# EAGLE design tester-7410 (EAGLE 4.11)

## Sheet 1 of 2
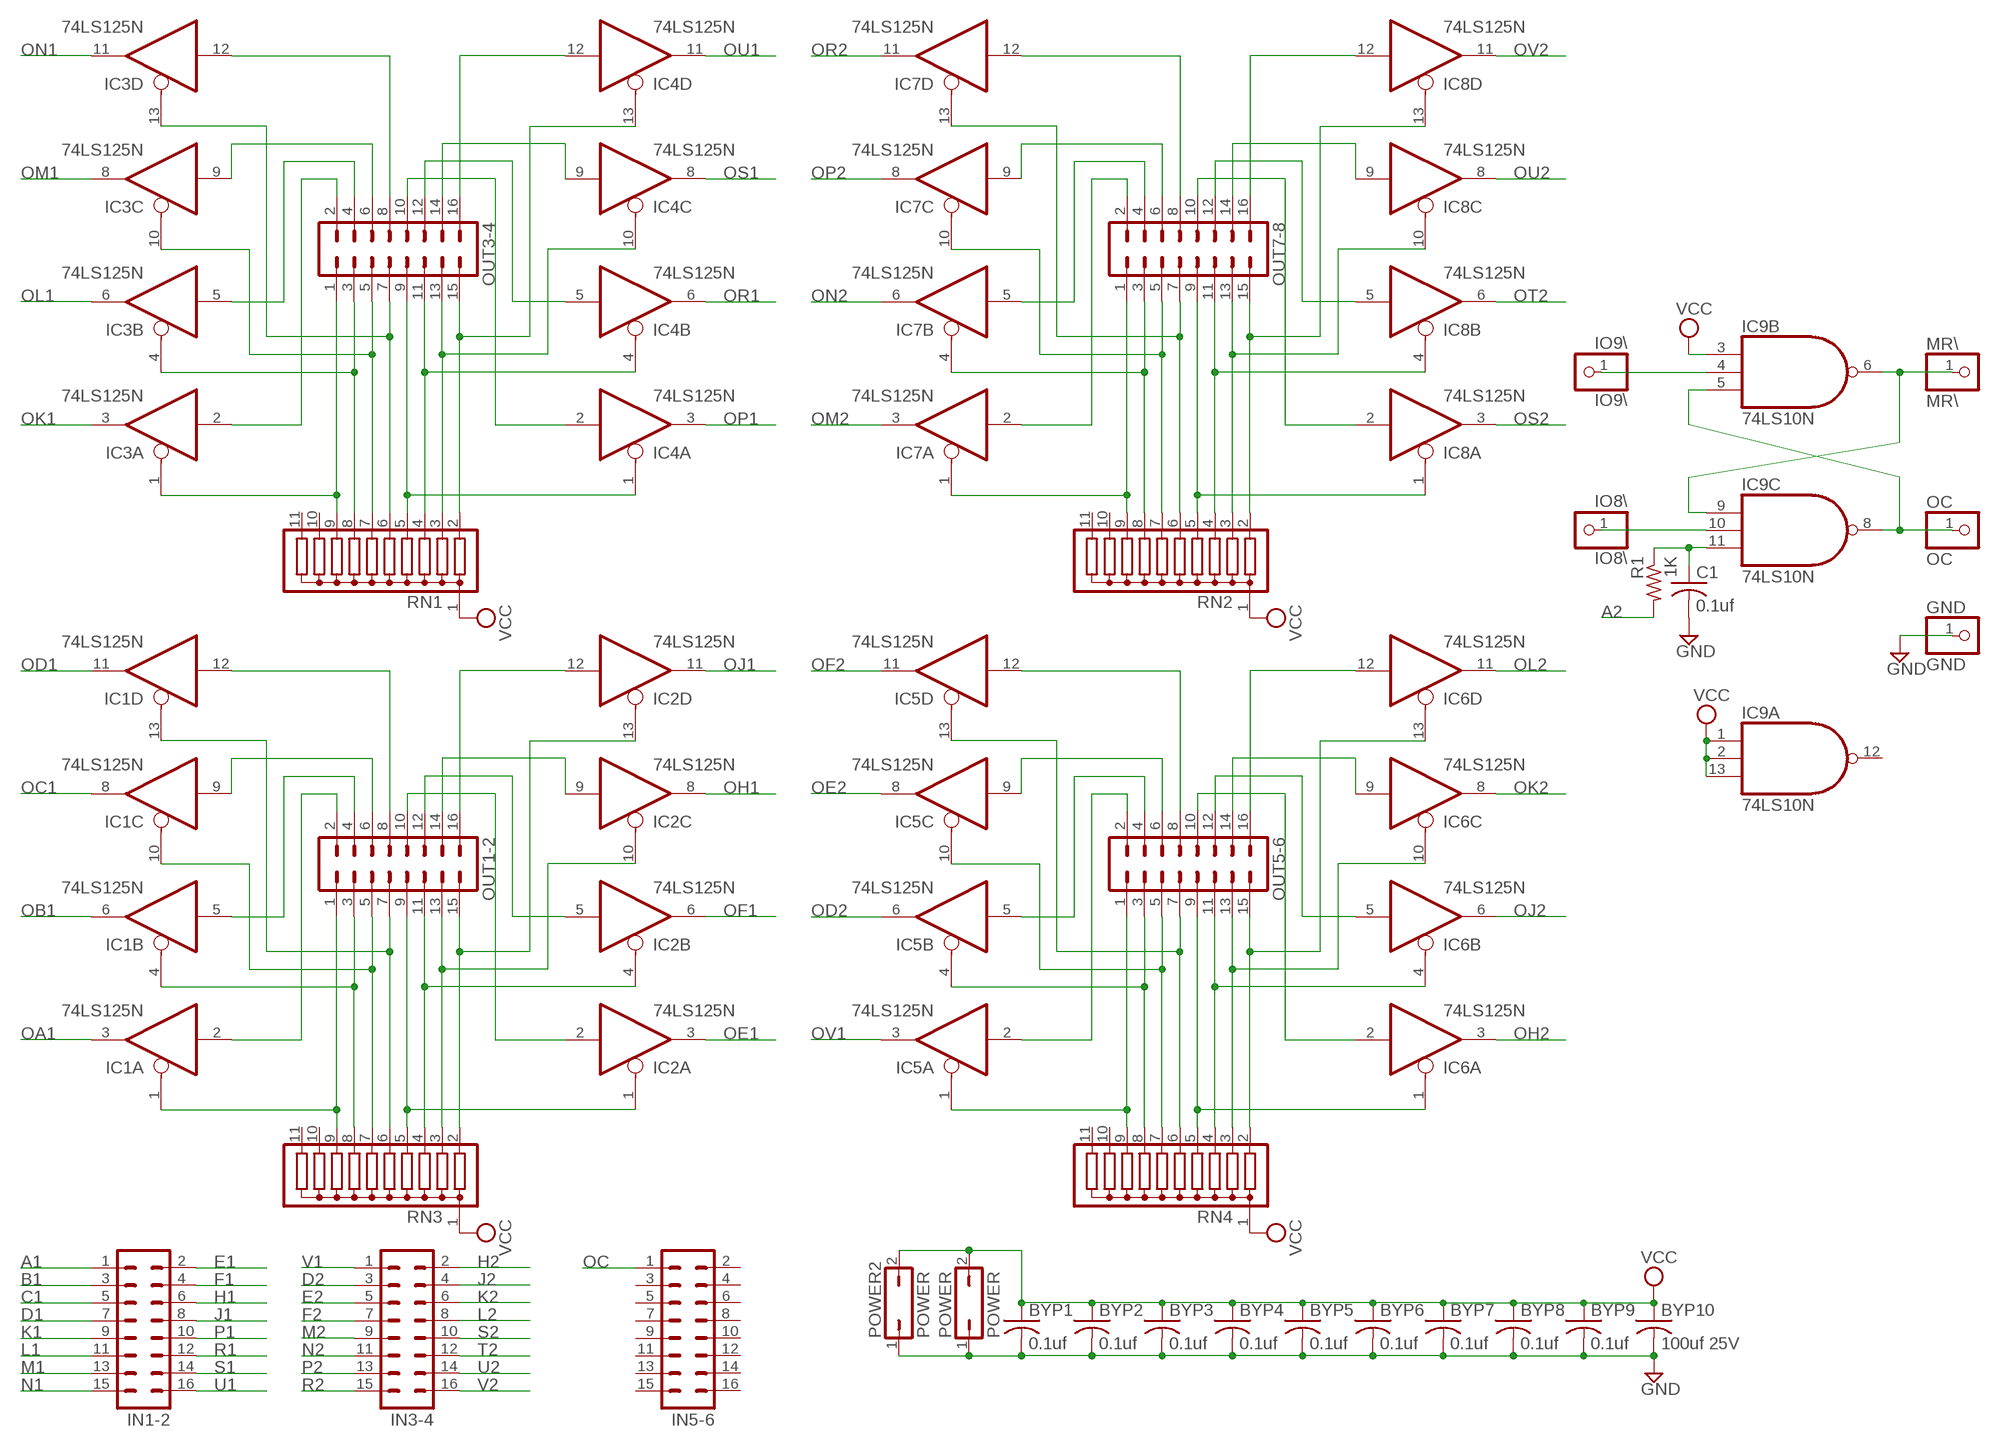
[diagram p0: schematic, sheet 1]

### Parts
BYP1  0.1uf  C-US050-025X075  [C050-025X075]
BYP2  0.1uf  C-US050-025X075  [C050-025X075]
BYP3  0.1uf  C-US050-025X075  [C050-025X075]
BYP4  0.1uf  C-US050-025X075  [C050-025X075]
BYP5  0.1uf  C-US050-025X075  [C050-025X075]
BYP6  0.1uf  C-US050-025X075  [C050-025X075]
BYP7  0.1uf  C-US050-025X075  [C050-025X075]
BYP8  0.1uf  C-US050-025X075  [C050-025X075]
BYP9  0.1uf  C-US050-025X075  [C050-025X075]
BYP10  100uf 25V  C-US150-064X183  [C150-064X183]
C1  0.1uf  C-US050-025X075  [C050-025X075]
GND  GND  PINHD-1X1  [1X01]
IC1  74LS125N  [DIL14]
IC2  74LS125N  [DIL14]
IC3  74LS125N  [DIL14]
IC4  74LS125N  [DIL14]
IC5  74LS125N  [DIL14]
IC6  74LS125N  [DIL14]
IC7  74LS125N  [DIL14]
IC8  74LS125N  [DIL14]
IC9  74LS10N  [DIL14]
IN1-2  MA08-2  [MA08-2]
IN3-4  MA08-2  [MA08-2]
IN5-6  MA08-2  [MA08-2]
IO8\  IO8\  PINHD-1X1  [1X01]
IO9\  IO9\  PINHD-1X1  [1X01]
MR\  MR\  PINHD-1X1  [1X01]
OC  OC  PINHD-1X1  [1X01]
OUT1-2  MA08-2  [MA08-2]
OUT3-4  MA08-2  [MA08-2]
OUT5-6  MA08-2  [MA08-2]
OUT7-8  MA08-2  [MA08-2]
POWER  POWER  JP1Q  [JP1]
POWER2  POWER  JP1Q  [JP1]
R1  1K  R-US_0207/10  [0207/10]
RN1  G10R  [SIL11]
RN2  G10R  [SIL11]
RN3  G10R  [SIL11]
RN4  G10R  [SIL11]

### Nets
A1: IN1-2.1 ; also sheet 2
A2: R1.2 ; also sheet 2
B1: IN1-2.3 ; also sheet 2
C1: IN1-2.5 ; also sheet 2
D1: IN1-2.7 ; also sheet 2
D2: IN3-4.3 ; also sheet 2
E1: IN1-2.2 ; also sheet 2
E2: IN3-4.5 ; also sheet 2
F1: IN1-2.4 ; also sheet 2
F2: IN3-4.7 ; also sheet 2
GND [Power]: BYP1.2 BYP2.2 BYP3.2 BYP4.2 BYP5.2 BYP6.2 BYP7.2 BYP8.2 BYP9.2 BYP10.2 C1.2 GND.1 POWER2.1 POWER.1 ; also sheet 2
H1: IN1-2.6 ; also sheet 2
H2: IN3-4.2 ; also sheet 2
IO8\: IC9.10(C:I1) IO8\.1
IO9\: IC9.4(B:I1) IO9\.1
J1: IN1-2.8 ; also sheet 2
J2: IN3-4.4 ; also sheet 2
K1: IN1-2.9 ; also sheet 2
K2: IN3-4.6 ; also sheet 2
L1: IN1-2.11 ; also sheet 2
L2: IN3-4.8 ; also sheet 2
M1: IN1-2.13 ; also sheet 2
M2: IN3-4.9 ; also sheet 2
MR\: IC9.6(B:O) IC9.9(C:I0) MR\.1
N1: IN1-2.15 ; also sheet 2
N2: IN3-4.11 ; also sheet 2
N$5: C1.1 IC9.11(C:I2) R1.1
N$53: IC1.1(A:OE) OUT1-2.1 RN3.9
N$54: IC1.4(B:OE) OUT1-2.3 RN3.8
N$55: IC1.10(C:OE) OUT1-2.5 RN3.7
N$56: IC1.13(D:OE) OUT1-2.7 RN3.6
N$57: IC1.2(A:I) OUT1-2.2
N$58: IC1.5(B:I) OUT1-2.4
N$59: IC1.9(C:I) OUT1-2.6
N$60: IC1.12(D:I) OUT1-2.8
N$61: IC5.4(B:OE) OUT5-6.3 RN4.8
N$62: IC2.10(C:OE) OUT1-2.13 RN3.3
N$63: IC2.4(B:OE) OUT1-2.11 RN3.4
N$64: IC2.1(A:OE) OUT1-2.9 RN3.5
N$65: IC2.2(A:I) OUT1-2.10
N$66: IC2.5(B:I) OUT1-2.12
N$67: IC2.9(C:I) OUT1-2.14
N$68: IC2.12(D:I) OUT1-2.16
N$138: IC5.13(D:OE) OUT5-6.7 RN4.6
N$139: IC2.13(D:OE) OUT1-2.15 RN3.2
N$140: IC5.2(A:I) OUT5-6.2
N$141: IC5.5(B:I) OUT5-6.4
N$142: IC5.9(C:I) OUT5-6.6
N$143: IC5.12(D:I) OUT5-6.8
N$144: IC6.10(C:OE) OUT5-6.13 RN4.3
N$145: IC6.4(B:OE) OUT5-6.11 RN4.4
N$146: IC6.1(A:OE) OUT5-6.9 RN4.5
N$147: IC6.2(A:I) OUT5-6.10
N$148: IC6.9(C:I) OUT5-6.14
N$149: IC6.12(D:I) OUT5-6.16
N$150: IC5.1(A:OE) OUT5-6.1 RN4.9
N$151: IC5.10(C:OE) OUT5-6.5 RN4.7
N$152: IC6.5(B:I) OUT5-6.12
N$153: IC6.13(D:OE) OUT5-6.15 RN4.2
N$154: IC3.4(B:OE) OUT3-4.3 RN1.8
N$155: IC3.13(D:OE) OUT3-4.7 RN1.6
N$156: IC3.2(A:I) OUT3-4.2
N$157: IC3.5(B:I) OUT3-4.4
N$158: IC3.9(C:I) OUT3-4.6
N$159: IC3.12(D:I) OUT3-4.8
N$160: IC4.10(C:OE) OUT3-4.13 RN1.3
N$161: IC4.4(B:OE) OUT3-4.11 RN1.4
N$162: IC4.1(A:OE) OUT3-4.9 RN1.5
N$163: IC4.2(A:I) OUT3-4.10
N$164: IC4.9(C:I) OUT3-4.14
N$165: IC4.12(D:I) OUT3-4.16
N$166: IC3.1(A:OE) OUT3-4.1 RN1.9
N$167: IC3.10(C:OE) OUT3-4.5 RN1.7
N$168: IC4.5(B:I) OUT3-4.12
N$169: IC4.13(D:OE) OUT3-4.15 RN1.2
N$170: IC7.4(B:OE) OUT7-8.3 RN2.8
N$171: IC7.13(D:OE) OUT7-8.7 RN2.6
N$172: IC7.2(A:I) OUT7-8.2
N$173: IC7.5(B:I) OUT7-8.4
N$174: IC7.9(C:I) OUT7-8.6
N$175: IC7.12(D:I) OUT7-8.8
N$176: IC8.10(C:OE) OUT7-8.13 RN2.3
N$177: IC8.4(B:OE) OUT7-8.11 RN2.4
N$178: IC8.1(A:OE) OUT7-8.9 RN2.5
N$179: IC8.2(A:I) OUT7-8.10
N$180: IC8.9(C:I) OUT7-8.14
N$181: IC8.12(D:I) OUT7-8.16
N$182: IC7.1(A:OE) OUT7-8.1 RN2.9
N$183: IC7.10(C:OE) OUT7-8.5 RN2.7
N$184: IC8.5(B:I) OUT7-8.12
N$185: IC8.13(D:OE) OUT7-8.15 RN2.2
OA1: IC1.3(A:O) ; also sheet 2
OB1: IC1.6(B:O) ; also sheet 2
OC: IC9.5(B:I2) IC9.8(C:O) IN5-6.1 OC.1
OC1: IC1.8(C:O) ; also sheet 2
OD1: IC1.11(D:O) ; also sheet 2
OD2: IC5.6(B:O) ; also sheet 2
OE1: IC2.3(A:O) ; also sheet 2
OE2: IC5.8(C:O) ; also sheet 2
OF1: IC2.6(B:O) ; also sheet 2
OF2: IC5.11(D:O) ; also sheet 2
OH1: IC2.8(C:O) ; also sheet 2
OH2: IC6.3(A:O) ; also sheet 2
OJ1: IC2.11(D:O) ; also sheet 2
OJ2: IC6.6(B:O) ; also sheet 2
OK1: IC3.3(A:O) ; also sheet 2
OK2: IC6.8(C:O) ; also sheet 2
OL1: IC3.6(B:O) ; also sheet 2
OL2: IC6.11(D:O) ; also sheet 2
OM1: IC3.8(C:O) ; also sheet 2
OM2: IC7.3(A:O) ; also sheet 2
ON1: IC3.11(D:O) ; also sheet 2
ON2: IC7.6(B:O) ; also sheet 2
OP1: IC4.3(A:O) ; also sheet 2
OP2: IC7.8(C:O) ; also sheet 2
OR1: IC4.6(B:O) ; also sheet 2
OR2: IC7.11(D:O) ; also sheet 2
OS1: IC4.8(C:O) ; also sheet 2
OS2: IC8.3(A:O) ; also sheet 2
OT2: IC8.6(B:O) ; also sheet 2
OU1: IC4.11(D:O) ; also sheet 2
OU2: IC8.8(C:O) ; also sheet 2
OV1: IC5.3(A:O) ; also sheet 2
OV2: IC8.11(D:O) ; also sheet 2
P1: IN1-2.10 ; also sheet 2
P2: IN3-4.13 ; also sheet 2
R1: IN1-2.12 ; also sheet 2
R2: IN3-4.15 ; also sheet 2
S1: IN1-2.14 ; also sheet 2
S2: IN3-4.10 ; also sheet 2
T2: IN3-4.12 ; also sheet 2
U1: IN1-2.16 ; also sheet 2
U2: IN3-4.14 ; also sheet 2
V1: IN3-4.1 ; also sheet 2
V2: IN3-4.16 ; also sheet 2
VCC [Power]: BYP1.1 BYP2.1 BYP3.1 BYP4.1 BYP5.1 BYP6.1 BYP7.1 BYP8.1 BYP9.1 BYP10.1 IC9.1(A:I0) IC9.2(A:I1) IC9.3(B:I0) IC9.13(A:I2) POWER2.2 POWER.2 RN1.1 RN2.1 RN3.1 RN4.1 ; also sheet 2
Unconnected: IC9.12(A:O) IN5-6.2 IN5-6.3 IN5-6.4 IN5-6.5 IN5-6.6 IN5-6.7 IN5-6.8 IN5-6.9 IN5-6.10 IN5-6.11 IN5-6.12 IN5-6.13 IN5-6.14 IN5-6.15 IN5-6.16 RN1.10 RN1.11 RN2.10 RN2.11 RN3.10 RN3.11 RN4.10 RN4.11

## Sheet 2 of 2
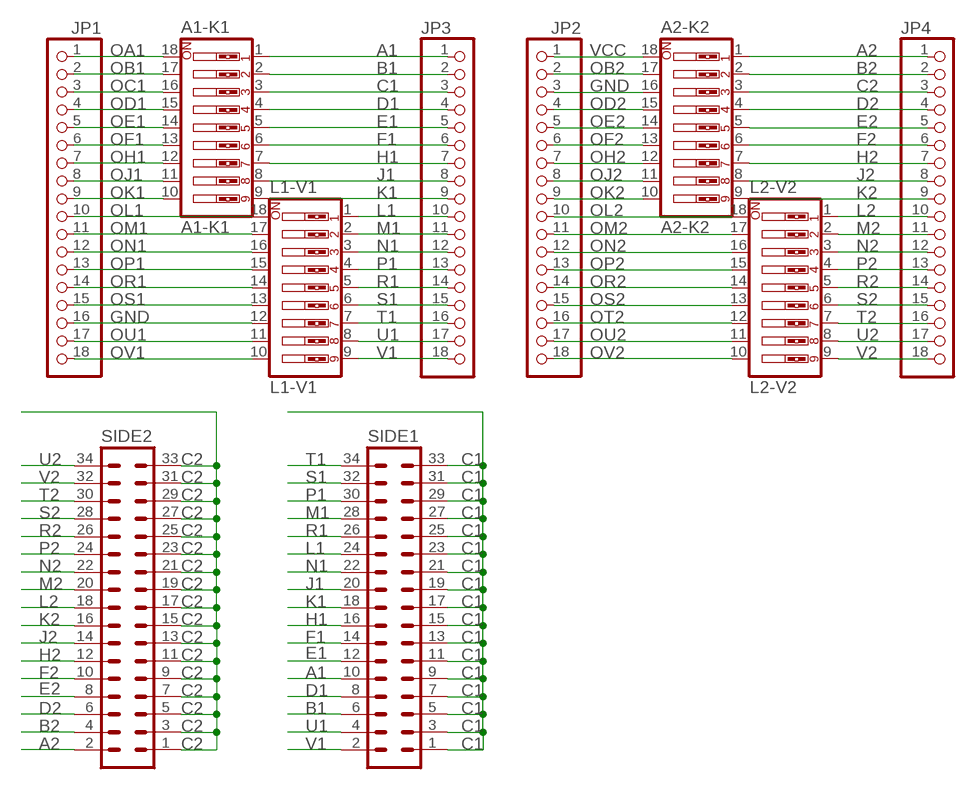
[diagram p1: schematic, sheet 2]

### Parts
A1-K1  A1-K1  SW_DIP-9  [EDG-09]
A2-K2  A2-K2  SW_DIP-9  [EDG-09]
JP1  PINHD-1X18  [1X18]
JP2  PINHD-1X18  [1X18]
JP3  PINHD-1X18  [1X18]
JP4  PINHD-1X18  [1X18]
L1-V1  L1-V1  SW_DIP-9  [EDG-09]
L2-V2  L2-V2  SW_DIP-9  [EDG-09]
SIDE1  MA17-2  [MA17-2]
SIDE2  MA17-2  [MA17-2]

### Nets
A1: A1-K1.1 JP3.1 SIDE1.10 ; also sheet 1
A2: A2-K2.1 JP4.1 SIDE2.2 ; also sheet 1
B1: A1-K1.2 JP3.2 SIDE1.6 ; also sheet 1
B2: A2-K2.2 JP4.2 SIDE2.4
C1: A1-K1.3 JP3.3 SIDE1.1 SIDE1.3 SIDE1.5 SIDE1.7 SIDE1.9 SIDE1.11 SIDE1.13 SIDE1.15 SIDE1.17 SIDE1.19 SIDE1.21 SIDE1.23 SIDE1.25 SIDE1.27 SIDE1.29 SIDE1.31 SIDE1.33 ; also sheet 1
C2: A2-K2.3 JP4.3 SIDE2.1 SIDE2.3 SIDE2.5 SIDE2.7 SIDE2.9 SIDE2.11 SIDE2.13 SIDE2.15 SIDE2.17 SIDE2.19 SIDE2.21 SIDE2.23 SIDE2.25 SIDE2.27 SIDE2.29 SIDE2.31 SIDE2.33
D1: A1-K1.4 JP3.4 SIDE1.8 ; also sheet 1
D2: A2-K2.4 JP4.4 SIDE2.6 ; also sheet 1
E1: A1-K1.5 JP3.5 SIDE1.12 ; also sheet 1
E2: A2-K2.5 JP4.5 SIDE2.8 ; also sheet 1
F1: A1-K1.6 JP3.6 SIDE1.14 ; also sheet 1
F2: A2-K2.6 JP4.6 SIDE2.10 ; also sheet 1
GND [Power]: A2-K2.16 JP1.16 JP2.3 L1-V1.12 ; also sheet 1
H1: A1-K1.7 JP3.7 SIDE1.16 ; also sheet 1
H2: A2-K2.7 JP4.7 SIDE2.12 ; also sheet 1
J1: A1-K1.8 JP3.8 SIDE1.20 ; also sheet 1
J2: A2-K2.8 JP4.8 SIDE2.14 ; also sheet 1
K1: A1-K1.9 JP3.9 SIDE1.18 ; also sheet 1
K2: A2-K2.9 JP4.9 SIDE2.16 ; also sheet 1
L1: JP3.10 L1-V1.1 SIDE1.24 ; also sheet 1
L2: JP4.10 L2-V2.1 SIDE2.18 ; also sheet 1
M1: JP3.11 L1-V1.2 SIDE1.28 ; also sheet 1
M2: JP4.11 L2-V2.2 SIDE2.20 ; also sheet 1
N1: JP3.12 L1-V1.3 SIDE1.22 ; also sheet 1
N2: JP4.12 L2-V2.3 SIDE2.22 ; also sheet 1
OA1: A1-K1.18 JP1.1 ; also sheet 1
OB1: A1-K1.17 JP1.2 ; also sheet 1
OB2: A2-K2.17 JP2.2
OC1: A1-K1.16 JP1.3 ; also sheet 1
OD1: A1-K1.15 JP1.4 ; also sheet 1
OD2: A2-K2.15 JP2.4 ; also sheet 1
OE1: A1-K1.14 JP1.5 ; also sheet 1
OE2: A2-K2.14 JP2.5 ; also sheet 1
OF1: A1-K1.13 JP1.6 ; also sheet 1
OF2: A2-K2.13 JP2.6 ; also sheet 1
OH1: A1-K1.12 JP1.7 ; also sheet 1
OH2: A2-K2.12 JP2.7 ; also sheet 1
OJ1: A1-K1.11 JP1.8 ; also sheet 1
OJ2: A2-K2.11 JP2.8 ; also sheet 1
OK1: A1-K1.10 JP1.9 ; also sheet 1
OK2: A2-K2.10 JP2.9 ; also sheet 1
OL1: JP1.10 L1-V1.18 ; also sheet 1
OL2: JP2.10 L2-V2.18 ; also sheet 1
OM1: JP1.11 L1-V1.17 ; also sheet 1
OM2: JP2.11 L2-V2.17 ; also sheet 1
ON1: JP1.12 L1-V1.16 ; also sheet 1
ON2: JP2.12 L2-V2.16 ; also sheet 1
OP1: JP1.13 L1-V1.15 ; also sheet 1
OP2: JP2.13 L2-V2.15 ; also sheet 1
OR1: JP1.14 L1-V1.14 ; also sheet 1
OR2: JP2.14 L2-V2.14 ; also sheet 1
OS1: JP1.15 L1-V1.13 ; also sheet 1
OS2: JP2.15 L2-V2.13 ; also sheet 1
OT2: JP2.16 L2-V2.12 ; also sheet 1
OU1: JP1.17 L1-V1.11 ; also sheet 1
OU2: JP2.17 L2-V2.11 ; also sheet 1
OV1: JP1.18 L1-V1.10 ; also sheet 1
OV2: JP2.18 L2-V2.10 ; also sheet 1
P1: JP3.13 L1-V1.4 SIDE1.30 ; also sheet 1
P2: JP4.13 L2-V2.4 SIDE2.24 ; also sheet 1
R1: JP3.14 L1-V1.5 SIDE1.26 ; also sheet 1
R2: JP4.14 L2-V2.5 SIDE2.26 ; also sheet 1
S1: JP3.15 L1-V1.6 SIDE1.32 ; also sheet 1
S2: JP4.15 L2-V2.6 SIDE2.28 ; also sheet 1
T1: JP3.16 L1-V1.7 SIDE1.34
T2: JP4.16 L2-V2.7 SIDE2.30 ; also sheet 1
U1: JP3.17 L1-V1.8 SIDE1.4 ; also sheet 1
U2: JP4.17 L2-V2.8 SIDE2.34 ; also sheet 1
V1: JP3.18 L1-V1.9 SIDE1.2 ; also sheet 1
V2: JP4.18 L2-V2.9 SIDE2.32 ; also sheet 1
VCC [Power]: A2-K2.18 JP2.1 ; also sheet 1

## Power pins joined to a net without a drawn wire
GND: IC1.7(P:GND) IC2.7(P:GND) IC3.7(P:GND) IC4.7(P:GND) IC5.7(P:GND) IC6.7(P:GND) IC7.7(P:GND) IC8.7(P:GND) IC9.7(P:GND)
VCC: IC1.14(P:VCC) IC2.14(P:VCC) IC3.14(P:VCC) IC4.14(P:VCC) IC5.14(P:VCC) IC6.14(P:VCC) IC7.14(P:VCC) IC8.14(P:VCC) IC9.14(P:VCC)

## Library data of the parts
A1-K1 A2-K2 L1-V1 L2-V2 = special:SW_DIP-9: DIP SWITCH
BYP1-BYP10 C1 = rcl:C-US: CAPACITOR, American symbol
GND IO8\ IO9\ MR\ OC = pinhead:PINHD-1X1: PIN HEADER
IC1-IC8 = 74xx-jameco:74*125: Quad bus BUFFER, 3-state
IC9 = 74xx-jameco:74*10: Triple 3-input NAND gate
IN1-2 IN3-4 IN5-6 OUT1-2 OUT3-4 OUT5-6 OUT7-8 = con-lstb:MA08-2: PIN HEADER
JP1-JP4 = pinhead:PINHD-1X18: PIN HEADER
POWER POWER2 = jumper:JP1Q: JUMPER
R1 = rcl:R-US_: RESISTOR, American symbol
RN1-RN4 = resistor-sil:G10R: SIL RESISTOR
SIDE1 SIDE2 = con-lstb:MA17-2: PIN HEADER

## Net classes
1 Power: width 0.305 mm, drill 0.305 mm

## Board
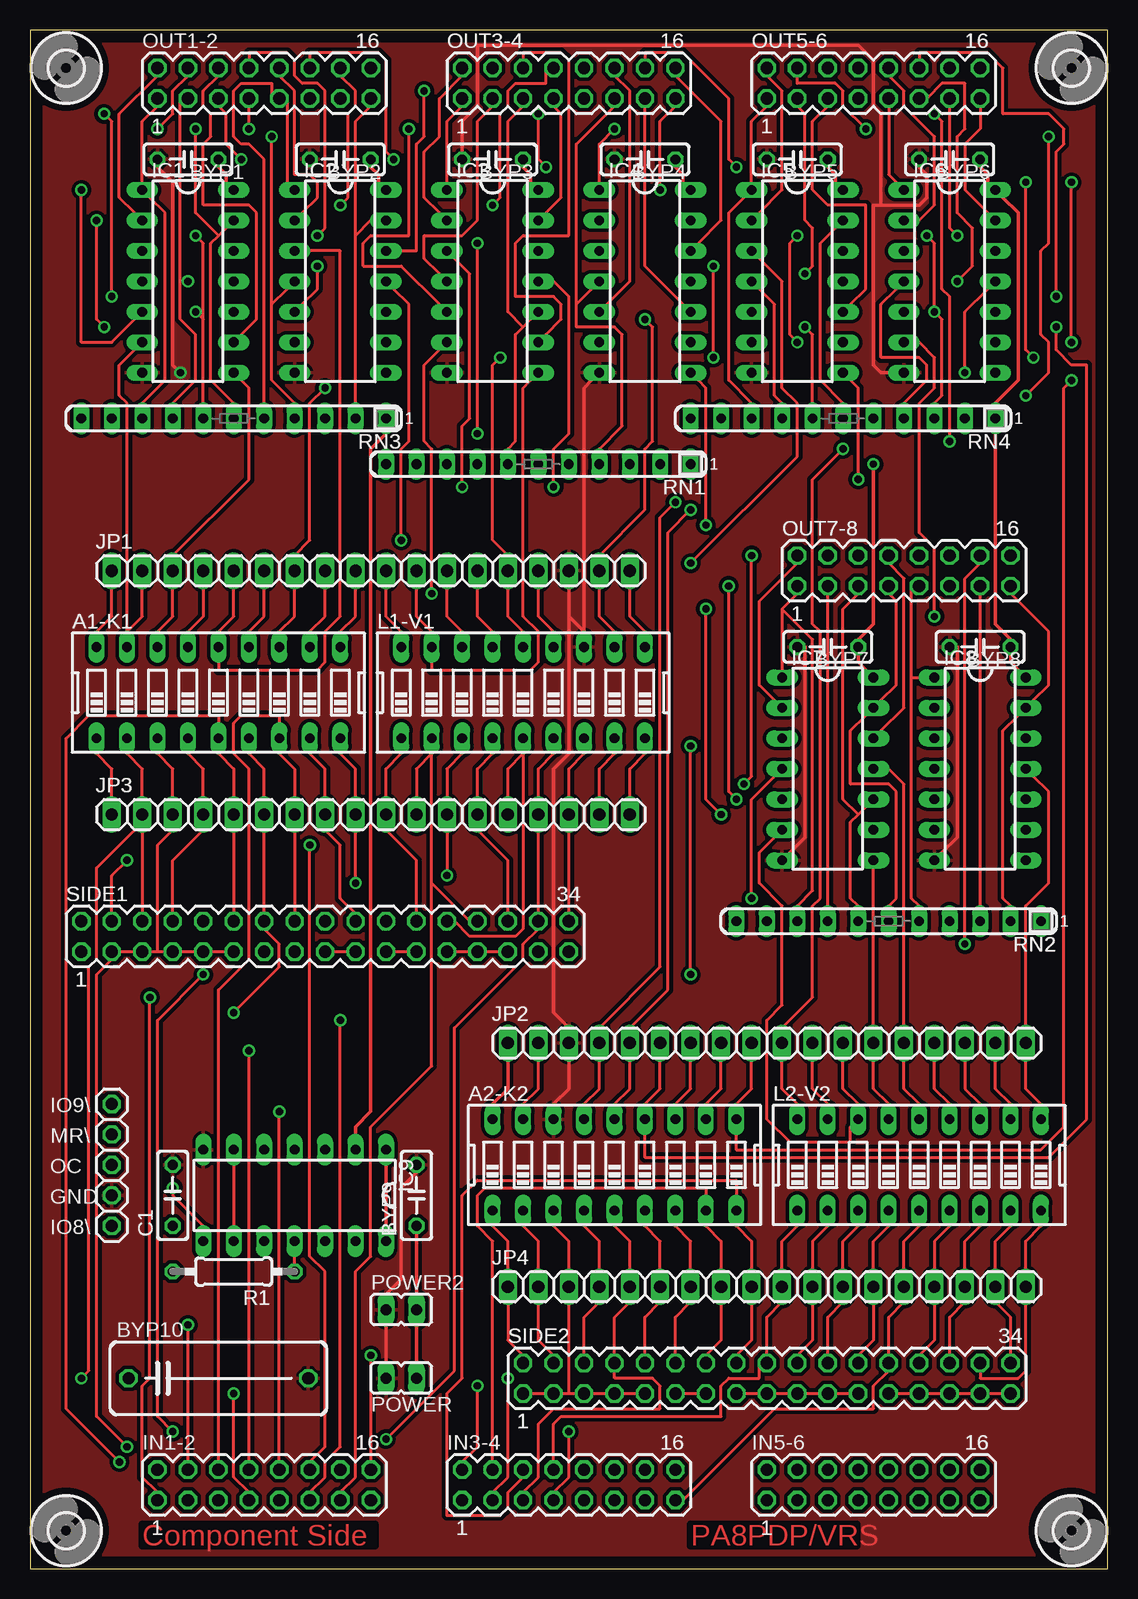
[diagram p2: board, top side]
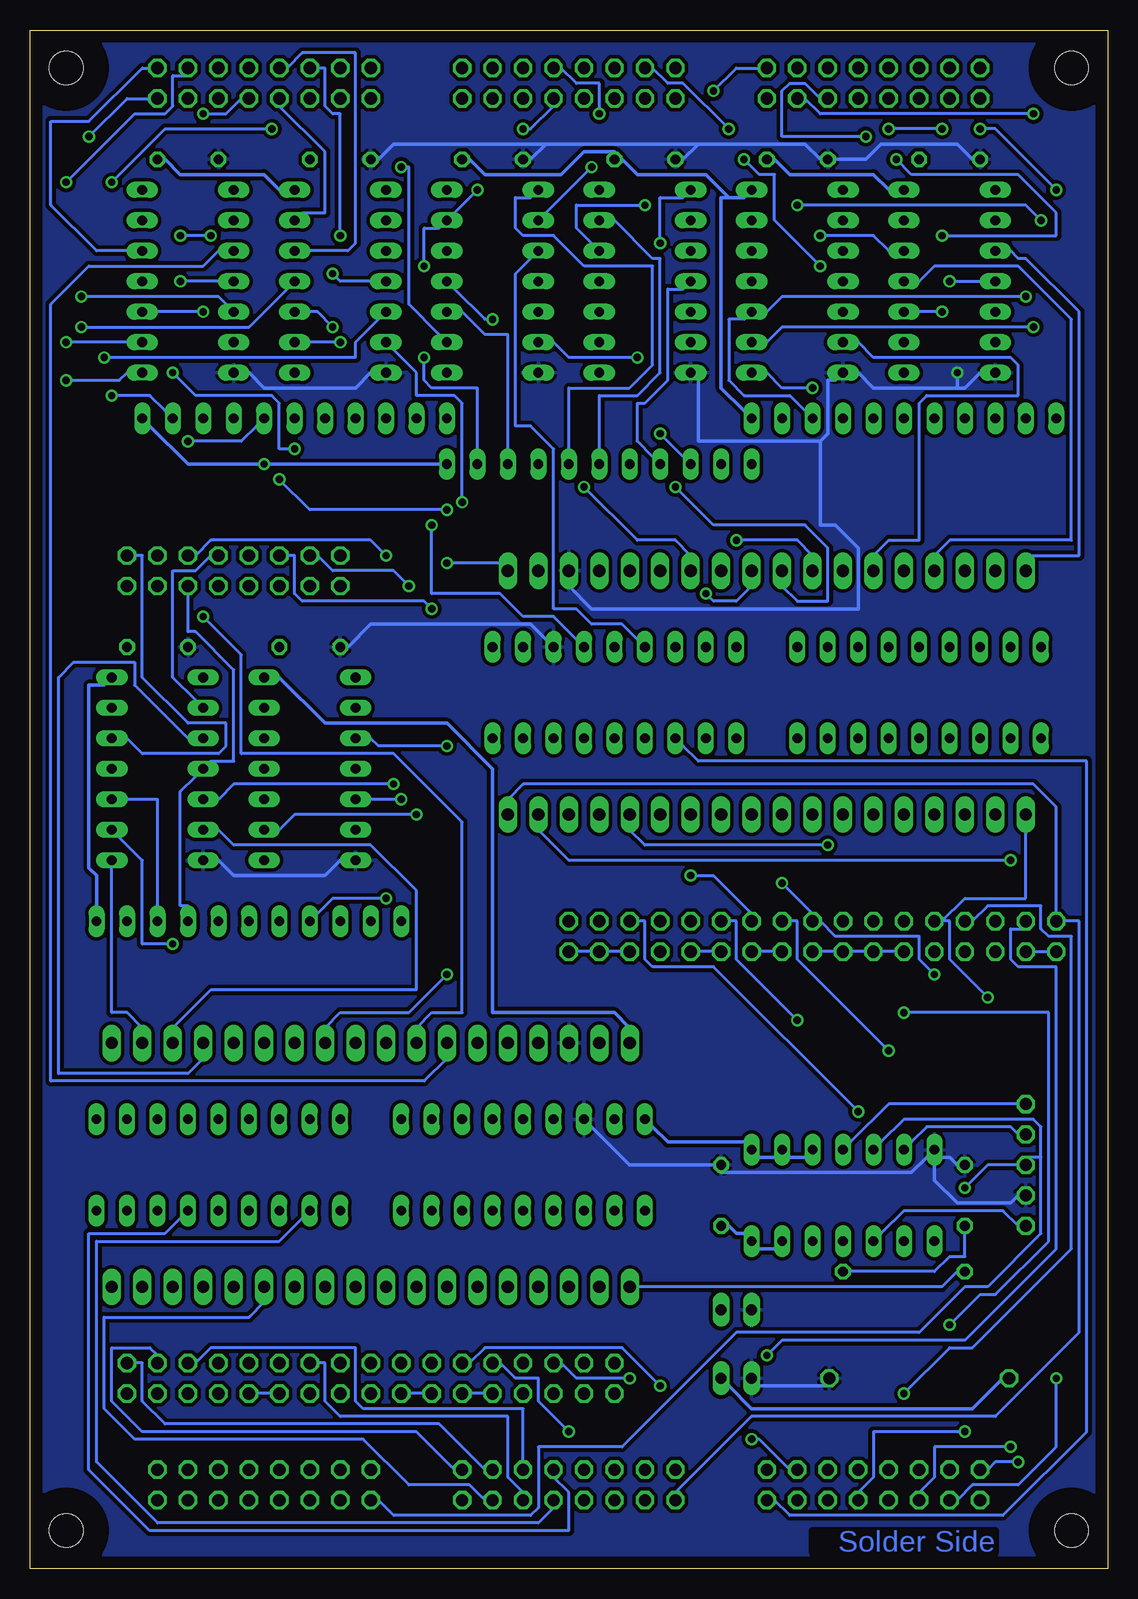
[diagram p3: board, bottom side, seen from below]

Size 89.84 x 128.25 mm. Coordinates in mm from the lower left corner, seen from the top.
Outline: 0,128.25 0,0 89.84,0 89.84,128.25 0,128.25
Copper layers (1*16): Top 0.035mm / dielectric 1.5mm / Bottom 0.035mm
Design rules "custompcb": minimum track width 10mil, minimum drill 24mil, track to track 12mil, track to pad 12mil, pad to pad 12mil, via to via 12mil, smd to smd 12mil, copper to edge 40mil, drill to drill 12mil, minimum pad ring 10mil, minimum via ring 8mil, stop-mask expansion 0mil, vias tented up to drill 0mil, thermal gap 10mil

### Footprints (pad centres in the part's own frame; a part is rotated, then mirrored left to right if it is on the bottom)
EDG-09 = drill 0.813 long: 1 -10.16,-3.81; 2 -7.62,-3.81; 3 -5.08,-3.81; 4 -2.54,-3.81; 5 0,-3.81; 6 2.54,-3.81; 7 5.08,-3.81; 8 7.62,-3.81; 9 10.16,-3.81; 10 10.16,3.81; 11 7.62,3.81; 12 5.08,3.81; 13 2.54,3.81; 14 0,3.81; 15 -2.54,3.81; 16 -5.08,3.81; 17 -7.62,3.81; 18 -10.16,3.81
C050-025X075 = drill 0.813 octagon: 1 -2.54,0; 2 2.54,0
C150-064X183 = drill 1.016 octagon: 1 -7.493,0; 2 7.493,0
1X01 = drill 1.016 octagon: 1 0,0
DIL14 = drill 0.813 long: 1 -7.62,-3.81; 2 -5.08,-3.81; 3 -2.54,-3.81; 4 0,-3.81; 5 2.54,-3.81; 6 5.08,-3.81; 7 7.62,-3.81; 8 7.62,3.81; 9 5.08,3.81; 10 2.54,3.81; 11 0,3.81; 12 -2.54,3.81; 13 -5.08,3.81; 14 -7.62,3.81
MA08-2 = drill 1.016 octagon: 1 -8.89,-1.27; 2 -8.89,1.27; 3 -6.35,-1.27; 4 -6.35,1.27; 5 -3.81,-1.27; 6 -3.81,1.27; 7 -1.27,-1.27; 8 -1.27,1.27; 9 1.27,-1.27; 10 1.27,1.27; 11 3.81,-1.27; 12 3.81,1.27; 13 6.35,-1.27; 14 6.35,1.27; 15 8.89,-1.27; 16 8.89,1.27
1X18 = drill 1.016 long: 1 -21.59,0; 2 -19.05,0; 3 -16.51,0; 4 -13.97,0; 5 -11.43,0; 6 -8.89,0; 7 -6.35,0; 8 -3.81,0; 9 -1.27,0; 10 1.27,0; 11 3.81,0; 12 6.35,0; 13 8.89,0; 14 11.43,0; 15 13.97,0; 16 16.51,0; 17 19.05,0; 18 21.59,0
JP1 = drill 0.914 long: 1 0,-1.27; 2 0,1.27
0207/10 = drill 0.813 octagon: 1 -5.08,0; 2 5.08,0
SIL11 = drill 0.813 long: 1 -12.7,0; 2 -10.16,0; 3 -7.62,0; 4 -5.08,0; 5 -2.54,0; 6 0,0; 7 2.54,0; 8 5.08,0; 9 7.62,0; 10 10.16,0; 11 12.7,0
MA17-2 = drill 1.016 octagon: 1 -20.32,-1.27; 2 -20.32,1.27; 3 -17.78,-1.27; 4 -17.78,1.27; 5 -15.24,-1.27; 6 -15.24,1.27; 7 -12.7,-1.27; 8 -12.7,1.27; 9 -10.16,-1.27; 10 -10.16,1.27; 11 -7.62,-1.27; 12 -7.62,1.27; 13 -5.08,-1.27; 14 -5.08,1.27; 15 -2.54,-1.27; 16 -2.54,1.27; 17 0,-1.27; 18 0,1.27; 19 2.54,-1.27; 20 2.54,1.27; 21 5.08,-1.27; 22 5.08,1.27; 23 7.62,-1.27; 24 7.62,1.27; 25 10.16,-1.27; 26 10.16,1.27; 27 12.7,-1.27; 28 12.7,1.27; 29 15.24,-1.27; 30 15.24,1.27; 31 17.78,-1.27; 32 17.78,1.27; 33 20.32,-1.27; 34 20.32,1.27
2,8 = hole 2.8: 0,0

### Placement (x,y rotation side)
A1-K1  15.71,73.01 0 top
A2-K2  48.73,33.64 0 top
BYP1  13.17,117.46 180 top
BYP2  25.87,117.46 180 top
BYP3  38.57,117.46 180 top
BYP4  51.27,117.46 180 top
BYP5  63.97,117.46 180 top
BYP6  76.67,117.46 180 top
BYP7  66.51,76.82 180 top
BYP8  79.21,76.82 180 top
BYP9  32.22,31.1 90 top
BYP10  15.71,15.86 0 top
C1  11.9,31.1 90 top
GND  6.82,31.1 90 top
IC1  13.17,107.3 270 top
IC2  25.87,107.3 270 top
IC3  38.57,107.3 270 top
IC4  51.27,107.3 270 top
IC5  63.97,107.3 270 top
IC6  76.67,107.3 270 top
IC7  66.51,66.66 270 top
IC8  79.21,66.66 270 top
IC9  22.06,31.1 180 top
IN1-2  19.52,6.97 0 top
IN3-4  44.92,6.97 0 top
IN5-6  70.32,6.97 0 top
IO8\  6.82,28.56 90 top
IO9\  6.82,38.72 90 top
JP1  28.41,83.17 0 top
JP2  61.43,43.8 0 top
JP3  28.41,62.85 0 top
JP4  61.43,23.48 0 top
L1-V1  41.11,73.01 0 top
L2-V2  74.13,33.64 0 top
MR\  6.82,36.18 90 top
OC  6.82,33.64 90 top
OUT1-2  19.52,123.81 0 top
OUT3-4  44.92,123.81 0 top
OUT5-6  70.32,123.81 0 top
OUT7-8  72.86,83.17 0 top
POWER  30.95,15.86 270 top
POWER2  30.95,21.57 270 top
R1  16.98,24.75 180 top
RN1  42.38,92.06 180 top
RN2  71.59,53.96 180 top
RN3  16.98,95.87 180 top
RN4  67.78,95.87 180 top
SIDE1  24.6,52.69 0 top
SIDE2  61.43,15.86 0 top
U$1  [2,8]  3.01,3.16 270 top
U$2  [2,8]  86.83,3.16 270 top
U$3  [2,8]  86.83,125.08 270 top
U$4  [2,8]  3.01,125.08 270 top

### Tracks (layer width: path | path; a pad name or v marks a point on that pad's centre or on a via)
A1  (via drill 0.61)
  Top 0.254: A1-K1.1 5.55,67.93 6.82,66.66 6.82,64.12 JP3.1 | v10,47.61 10,15.86 9.36,15.22 9.36,7.61 10.63,6.33 IN1-2.1
  Bottom 0.254: v10,47.61 13.17,50.78 13.17,53.96 13.81,53.96 | 13.81,53.96 SIDE1.10 13.81,53.96 | 13.81,53.96 11.9,55.87 6.82,55.87 6.82,61.58 JP3.1
A2
  Top 0.254: A2-K2.1 38.57,28.56 39.84,27.29 39.84,24.75 JP4.1 39.84,22.21 39.84,19.04 41.11,17.77 SIDE2.2
  Bottom 0.254: R1.2 12.54,24.75 13.81,23.48 39.2,23.48 JP4.1
B1  (via drill 0.61)
  Top 0.254: A1-K1.2 8.09,67.93 9.36,66.66 9.36,64.12 JP3.2 | SIDE1.6 9.36,54.59 9.36,61.58 JP3.2 | v4.28,15.86 4.92,16.5 4.92,50.15 5.55,50.78 5.55,58.41 8.73,61.58 8.73,62.21 JP3.2
  Bottom 0.254: v4.28,15.86 4.28,10.14 7.46,6.97 11.27,6.97 12.54,5.7 IN1-2.3
B2
  Top 0.254: A2-K2.2 41.11,28.56 42.38,27.29 42.38,24.75 JP4.2 42.38,22.21 42.38,19.04 43.65,17.77 SIDE2.4
C1  (via drill 0.61)
  Top 0.254: A1-K1.3 10.63,67.93 11.9,66.66 11.9,64.12 JP3.3 11.9,61.58 10.63,60.31 10.63,51.42 | v8.09,10.14 5.55,12.68 5.55,49.52 6.82,50.78 SIDE1.3 7.46,51.42 8.73,51.42 SIDE1.5 10,51.42 10.63,51.42 | 10.63,51.42 11.27,51.42 SIDE1.7 12.54,51.42 13.81,51.42 SIDE1.9 15.08,51.42 16.35,51.42 SIDE1.11 | SIDE1.19 26.51,51.42 25.23,51.42 SIDE1.17 | SIDE1.23 31.59,51.42 30.32,51.42 SIDE1.21 | SIDE1.25 35.4,51.42 36.66,51.42 SIDE1.27 37.94,51.42 39.2,51.42 SIDE1.29
  Bottom 0.254: v8.09,10.14 14.44,10.14 14.44,7.61 15.71,6.33 IN1-2.5 | SIDE1.1 4.92,51.42 6.18,51.42 SIDE1.3 | SIDE1.11 17.62,51.42 18.89,51.42 SIDE1.13 20.16,51.42 21.43,51.42 SIDE1.15 22.7,51.42 23.96,51.42 SIDE1.17 | SIDE1.21 29.05,51.42 27.78,51.42 SIDE1.19 | SIDE1.25 34.12,51.42 32.86,51.42 SIDE1.23 | SIDE1.29 40.48,51.42 41.74,51.42 SIDE1.31 43.02,51.42 44.29,51.42 SIDE1.33
C2
  Top 0.254: A2-K2.3 43.65,28.56 44.92,27.29 44.92,24.75 JP4.3 44.92,22.21 44.92,14.59 | SIDE2.1 41.74,14.59 43.02,14.59 SIDE2.3 44.29,14.59 44.92,14.59 | 44.92,14.59 45.55,14.59 SIDE2.5 46.83,14.59 48.09,14.59 SIDE2.7 49.37,14.59 50.63,14.59 SIDE2.9 | SIDE2.13 55.72,14.59 54.45,14.59 SIDE2.11 | SIDE2.15 59.52,14.59 60.8,14.59 SIDE2.17 62.06,14.59 63.34,14.59 SIDE2.19 64.6,14.59 65.88,14.59 SIDE2.21 67.14,14.59 68.41,14.59 SIDE2.23 | SIDE2.25 72.22,14.59 73.49,14.59 SIDE2.27 74.77,14.59 76.03,14.59 SIDE2.29 77.3,14.59 78.57,14.59 SIDE2.31 79.84,14.59 81.11,14.59 SIDE2.33
  Bottom 0.254: SIDE2.11 53.18,14.59 51.91,14.59 SIDE2.9 | SIDE2.15 58.26,14.59 56.98,14.59 SIDE2.13 | SIDE2.25 70.95,14.59 69.68,14.59 SIDE2.23
D1  (via drill 0.61)
  Top 0.254: A1-K1.4 13.17,67.93 14.44,66.66 14.44,64.12 JP3.4 14.44,61.58 11.9,59.04 11.9,54.59 SIDE1.8 | v16.98,14.59 16.98,7.61 18.25,6.33 IN1-2.7
  Bottom 0.254: v16.98,14.59 13.17,18.4 11.27,18.4 3.01,26.66 3.01,52.69 4.92,52.69 5.55,53.33 5.55,55.23 10,55.23 11.27,53.96 SIDE1.8
D2  (via drill 0.61)
  Top 0.254: A2-K2.4 46.19,28.56 47.46,27.29 47.46,24.75 JP4.4 47.46,22.21 46.19,20.94 46.19,17.77 SIDE2.6 | v39.84,15.86 39.84,7.61 38.57,6.33 IN3-4.3
  Bottom 0.254: v39.84,15.86 44.29,15.86 45.55,17.13 SIDE2.6
E1  (via drill 0.61)
  Top 0.254: v7.46,8.88 3.01,13.32 3.01,69.2 4.92,71.11 15.71,71.11 15.71,70.47 A1-K1.5 15.71,67.93 16.98,66.66 16.98,64.12 JP3.5 16.98,61.58 16.98,54.59 SIDE1.12
  Bottom 0.254: v7.46,8.88 9.36,8.88 10,8.24 IN1-2.2
E2
  Top 0.254: A2-K2.5 48.73,28.56 50,27.29 50,24.75 JP4.5 50,22.21 48.73,20.94 48.73,17.77 SIDE2.8 48.73,16.5 48.73,15.86 51.91,15.86 52.54,15.22 52.54,13.32 43.65,13.32 42.38,12.05 42.38,7.61 41.11,6.33 IN3-4.5
F1  (via drill 0.61)
  Top 0.254: A1-K1.6 18.25,67.93 19.52,66.66 19.52,64.12 JP3.6 19.52,61.58 19.52,54.59 SIDE1.14 19.52,53.33 20.79,52.05 20.79,50.15 v16.98,46.34 | v13.17,20.3 13.17,8.88 IN1-2.4
  Bottom 0.254: v13.17,20.3 10.63,22.84 9.36,22.84 4.92,27.29 4.92,46.34 v16.98,46.34
F2  (via drill 0.61)
  Top 0.254: A2-K2.6 51.27,28.56 52.54,27.29 52.54,24.75 JP4.6 52.54,22.21 51.27,20.94 51.27,17.77 SIDE2.10 | v44.92,11.41 44.92,7.61 43.65,6.33 IN3-4.7
  Bottom 0.254: v44.92,11.41 47.46,13.96 47.46,15.86 49.37,15.86 50.63,17.13 SIDE2.10
GND  (via drill 0.61)
  Top 0.305: 70.95,113.65 70.32,113.65 70.32,100.31 70.95,99.68 71.59,99.68 IC6.7 | 70.95,113.65 74.13,113.65 74.77,114.28 74.77,116.19 74.13,116.83 BYP6.2 | 70.95,113.65 70.95,121.27 70.32,121.91 70.32,125.72 69.05,126.98 37.3,126.98 37.3,121.91 36.03,120.64 36.03,118.09 BYP3.2 | A2-K2.16 43.65,38.72 44.92,39.99 44.92,42.53 JP2.3 44.92,45.07 43.65,46.34 43.65,66.66 44.92,67.93 44.92,79.36 | BYP9.2 32.22,33.01 30.95,31.73 30.95,24.11 29.68,22.84 POWER2.1 29.68,20.3 29.68,17.13 POWER.1 | 44.92,79.36 46.19,78.09 | 44.92,79.36 44.92,81.9 JP1.16 | 46.19,78.09 L1-V1.12 46.19,78.09 | 46.19,78.09 46.19,98.41 46.83,99.05 IC4.7 | IC7.7 63.34,59.67 64.6,60.95 64.6,76.82 BYP7.2 | IC8.7 76.03,59.67 77.3,60.95 77.3,76.82 BYP8.2 | v12.54,99.68 11.9,100.31 11.9,115.55 10.63,116.83 BYP1.2
  Bottom 0.305: IC5.7 61.43,99.68 62.7,98.41 70.32,98.41 71.59,99.68 IC6.7 | BYP1.2 11.27,117.46 12.54,118.73 18.89,118.73 20.16,117.46 22.7,117.46 BYP2.2 23.96,117.46 25.23,118.73 34.12,118.73 | 34.12,118.73 35.4,117.46 BYP3.2 | 46.83,118.73 48.09,117.46 BYP4.2 | 34.12,118.73 46.83,118.73 | 46.83,118.73 59.52,118.73 60.8,117.46 BYP5.2 | C1.2 12.54,33.64 13.17,34.27 13.81,34.27 IC9.7 | GND.1 7.46,31.1 8.09,30.46 12.54,30.46 14.44,32.37 14.44,33.64 IC9.7 | BYP10.2 23.33,15.22 29.05,15.22 POWER.1 | A2-K2.16 43.02,36.81 39.84,33.64 32.86,33.64 BYP9.2 32.22,33.01 16.35,33.01 15.08,34.27 IC9.7 | 12.54,98.41 19.52,98.41 20.79,99.68 IC2.7 22.7,99.05 23.33,99.05 23.33,94.6 23.96,93.97 | 12.54,98.41 11.9,98.41 10.63,99.68 IC1.7 | 23.96,93.97 34.12,93.97 34.12,99.05 IC3.7 | IC7.7 63.97,59.04 65.24,57.77 72.86,57.77 74.13,59.04 IC8.7 | L1-V1.12 46.83,77.45 48.09,78.72 61.43,78.72 63.34,76.82 BYP7.2 | 23.96,93.97 23.96,86.98 22.7,86.98 20.79,85.08 20.79,80 43.02,80 44.92,81.9 JP1.16 | 12.54,98.41 v12.54,99.68
  pour Bottom: -0.17,-0.01 -0.17,128.26 90,128.26 90,-0.01
  pour Top: -0.17,-0.01 -0.17,128.26 90,128.26 90,-0.01
H1
  Top 0.254: IN1-2.6 15.71,8.88 15.71,48.24 18.25,50.78 18.25,66.66 16.98,67.93 16.98,70.47 17.62,71.11 20.79,71.11 20.79,70.47 A1-K1.7 20.79,67.93 22.06,66.66 22.06,64.12 JP3.7 22.06,61.58 22.06,54.59 SIDE1.16
H2  (via drill 0.61)
  Top 0.254: A2-K2.7 53.81,28.56 55.08,27.29 55.08,24.75 JP4.7 55.08,22.21 53.81,20.94 53.81,17.77 SIDE2.12 | v37.3,15.22 37.3,10.14 36.03,8.88 IN3-4.2
  Bottom 0.254: v37.3,15.22 40.48,18.4 51.91,18.4 53.18,17.13 SIDE2.12
IO8\
  Bottom 0.254: IC9.10 18.89,27.93 16.98,29.83 8.73,29.83 7.46,28.56 IO8\.1
IO9\
  Bottom 0.254: IC9.4 21.43,35.55 18.25,38.72 7.46,38.72 IO9\.1
J1  (via drill 0.61)
  Top 0.254: A1-K1.8 23.33,67.93 24.6,66.66 24.6,64.12 JP3.8 24.6,61.58 25.87,60.31 25.87,55.87 27.14,54.59 SIDE1.20 | v18.25,43.16 18.25,8.88 IN1-2.8
  Bottom 0.254: v18.25,43.16 25.87,50.78 25.87,53.96 26.51,53.96 SIDE1.20
J2
  Top 0.254: IN3-4.4 38.57,8.88 38.57,27.29 37.3,28.56 37.3,31.1 37.94,31.73 56.35,31.73 56.35,31.1 A2-K2.8 56.35,28.56 57.62,27.29 57.62,24.75 JP4.8 57.62,22.21 57.62,19.04 56.35,17.77 SIDE2.14
K1  (via drill 0.61)
  Top 0.254: A1-K1.9 25.87,67.93 27.14,66.66 27.14,64.12 JP3.9 27.14,61.58 v27.14,57.13 | v11.9,11.41 10.63,12.68 10.63,45.7 v14.44,49.52
  Bottom 0.254: v11.9,11.41 19.52,11.41 19.52,7.61 20.79,6.33 IN1-2.9 | v14.44,49.52 15.71,50.78 15.71,52.69 22.7,52.69 23.96,53.96 SIDE1.18 24.6,54.59 v27.14,57.13
K2
  Top 0.254: IN3-4.6 41.11,7.61 39.84,6.33 39.84,5.07 39.2,4.43 34.76,4.43 34.76,14.59 36.03,15.86 36.03,31.1 37.3,32.37 58.89,32.37 58.89,31.1 A2-K2.9 58.89,28.56 60.16,27.29 60.16,24.75 JP4.9 60.16,22.21 60.16,19.04 58.89,17.77 SIDE2.16
L1  (via drill 0.61)
  Top 0.254: L1-V1.1 30.95,67.93 29.68,66.66 29.68,64.12 JP3.10 29.68,61.58 32.22,59.04 32.22,54.59 SIDE1.24 | v25.87,45.7 25.87,10.14 24.6,8.88 24.6,7.61 23.33,6.33 IN1-2.11
  Bottom 0.254: v25.87,45.7 30.95,50.78 30.95,53.96 31.59,53.96 SIDE1.24
L2
  Top 0.254: L2-V2.1 63.97,28.56 62.7,27.29 62.7,24.75 JP4.10 62.7,22.21 61.43,20.94 61.43,17.77 SIDE2.18 60.8,17.13 60.8,15.86 58.26,15.86 57.62,15.22 57.62,12.68 44.29,12.68 43.65,12.05 43.65,8.88 IN3-4.8
M1
  Top 0.254: 33.49,67.93 32.22,66.66 32.22,64.12 JP3.11 | 33.49,67.93 L1-V1.2 33.49,67.93 | 33.49,57.13 33.49,67.93 | 33.49,57.13 33.49,41.89 28.41,36.81 28.41,26.02 27.14,24.75 27.14,7.61 25.87,6.33 IN1-2.13 | 33.49,57.13 36.66,53.96 SIDE1.28
M2
  Top 0.254: L2-V2.2 66.51,28.56 65.24,27.29 65.24,24.75 JP4.11 65.24,22.21 65.24,19.04 63.97,17.77 SIDE2.20
  Bottom 0.254: IN3-4.9 46.19,5.07 47.46,3.79 79.21,3.79 84.29,8.88 84.29,27.29 69.05,27.29 67.14,29.2 L2-V2.2
MR\
  Top 0.254: IC9.9 16.98,28.56 16.98,33.64 IC9.6
  Bottom 0.254: MR\.1 7.46,36.18 8.09,36.81 15.08,36.81 16.35,35.55 IC9.6
N1  (via drill 0.61)
  Top 0.254: L1-V1.3 36.03,67.93 34.76,66.66 34.76,64.12 JP3.12 34.76,61.58 v34.76,57.77
  Bottom 0.254: IN1-2.15 27.78,5.7 26.51,4.43 8.73,4.43 1.74,11.41 1.74,67.3 34.12,67.3 35.4,68.56 L1-V1.3 | v34.76,57.77 32.86,57.77 29.68,54.59 SIDE1.22
N2
  Top 0.254: L2-V2.3 69.05,28.56 67.78,27.29 67.78,24.75 JP4.12 67.78,22.21 66.51,20.94 66.51,17.77 SIDE2.22
  Bottom 0.254: IN3-4.11 48.73,6.33 50,7.61 50,12.68 63.97,12.68 65.24,13.96 65.24,17.13 65.88,17.13 SIDE2.22
N$5
  Top 0.254: R1.1 22.06,25.38 22.06,26.02 IC9.11
  Bottom 0.254: C1.1 11.9,27.93 11.9,26.02 13.17,26.02 14.44,24.75 21.43,24.75 R1.1
N$53
  Top 0.254: RN3.9 9.36,97.14 11.27,99.05 11.27,113.02 10,114.28 IC1.1 9.36,115.55 9.36,120.64 10.63,121.91 OUT1-2.1
N$54  (via drill 0.61)
  Top 0.254: 12.54,107.3 12.54,122.54 OUT1-2.3 | 12.54,107.3 12.54,104.12 13.81,102.86 13.81,99.05 11.9,97.14 RN3.8 | 12.54,107.3 v13.17,107.3
  Bottom 0.254: v13.17,107.3 10.63,107.3 IC1.4
N$55  (via drill 0.61)
  Top 0.254: 14.44,104.12 14.44,97.14 RN3.7 | 14.44,104.12 v13.81,104.76 | v17.62,117.46 16.35,118.73 16.35,121.27 15.71,121.91 OUT1-2.5 | v13.81,111.11 14.44,110.47 14.44,104.12
  Bottom 0.254: v13.81,104.76 15.71,104.76 IC1.10 | v17.62,117.46 16.35,116.19 7.46,116.19 4.28,113.02 4.28,111.11 v13.81,111.11
N$56  (via drill 0.61)
  Top 0.254: 15.71,111.11 16.35,111.75 IC1.13 | 15.71,111.11 15.08,110.47 15.08,99.05 16.98,97.14 RN3.6 | v18.25,120 18.25,121.91 OUT1-2.7 | v13.81,120 13.81,113.02 15.71,111.11
  Bottom 0.254: v13.81,120 v18.25,120
N$57
  Top 0.254: IC1.2 8.73,113.02 7.46,114.28 7.46,121.27 10.63,124.44 OUT1-2.2
N$58  (via drill 0.61)
  Top 0.254: v4.28,114.92 4.28,102.22 6.82,102.22 8.73,104.12 IC1.5 | v10.63,120 11.9,121.27 11.9,123.17 13.17,124.44 OUT1-2.4
  Bottom 0.254: v4.28,114.92 9.36,120 v10.63,120
N$59
  Top 0.254: IC1.9 17.62,102.86 18.89,104.12 18.89,113.02 18.25,113.65 14.44,113.65 14.44,118.73 15.08,119.36 15.08,121.27 14.44,121.91 14.44,123.17 15.71,124.44 OUT1-2.6
N$60  (via drill 0.61)
  Top 0.254: v23.96,111.11 24.6,111.75 24.6,123.17 23.96,123.81 22.7,123.81 22.06,124.44 22.06,125.72 21.43,126.35 18.25,126.35 18.25,125.72 OUT1-2.8
  Bottom 0.254: v23.96,111.11 19.52,111.11 18.25,109.84 IC1.12
N$61  (via drill 0.61)
  Top 0.254: RN4.8 62.7,97.14 62.06,97.78 62.06,105.39 60.8,106.67 IC5.4 | v64.6,107.94 65.24,108.57 65.24,111.75 64.6,112.38 64.6,121.27 63.97,121.91 OUT5-6.3
  Bottom 0.254: v64.6,107.94 63.97,107.3 61.43,107.3 IC5.4
N$62  (via drill 0.61)
  Top 0.254: v6.18,121.27 6.82,120.64 v6.82,106.03
  Bottom 0.254: RN3.3 25.23,96.5 26.51,97.78 30.32,97.78 31.59,99.05 31.59,104.12 30.32,104.12 IC2.10 28.41,104.76 27.14,106.03 v6.82,106.03 | v6.18,121.27 23.96,121.27 25.23,122.54 OUT1-2.13
N$63  (via drill 0.61)
  Top 0.254: 20.16,105.39 20.16,99.05 22.06,97.14 RN3.4 | 20.16,105.39 21.43,106.67 IC2.4 | 20.16,105.39 v20.16,119.36
  Bottom 0.254: v20.16,119.36 27.14,119.36 27.14,123.17 26.51,123.81 25.23,123.81 23.96,122.54 OUT1-2.11
N$64
  Top 0.254: RN3.5 19.52,97.14 19.52,117.46 18.25,118.73 17.62,118.73 16.98,119.36 16.98,123.17 17.62,123.81 20.16,123.81 20.16,122.54 OUT1-2.9 21.43,122.54 21.43,115.55 IC2.1
N$65
  Top 0.254: IC2.2 22.7,113.02 23.96,114.28 23.96,115.55 23.33,116.19 22.06,116.19 22.06,123.17 20.79,124.44 OUT1-2.10
N$66  (via drill 0.61)
  Top 0.254: v23.96,108.57 23.96,106.67 22.7,105.39 IC2.5 | v30.32,117.46 29.68,118.09 29.68,125.72 29.05,126.35 23.33,126.35 23.33,125.72 OUT1-2.12
  Bottom 0.254: v23.96,108.57 27.78,112.38 27.78,116.19 29.05,116.19 v30.32,117.46
N$67  (via drill 0.61)
  Top 0.254: v6.18,103.49 5.55,104.12 v5.55,112.38 | v25.87,113.65 26.51,114.28 26.51,121.27 27.14,121.91 27.14,123.17 25.87,124.44 OUT1-2.14
  Bottom 0.254: v6.18,103.49 27.14,103.49 28.41,102.22 IC2.9 | v5.55,112.38 6.82,113.65 v25.87,113.65
N$68  (via drill 0.61)
  Top 0.254: v32.86,123.17 32.86,119.36 32.22,118.73 32.22,109.84 30.95,109.84 IC2.12
  Bottom 0.254: v32.86,123.17 30.95,125.08 29.05,125.08 OUT1-2.16
N$138
  Top 0.254: RN4.6 67.78,97.14 65.88,99.05 65.88,110.47 67.14,111.75 IC5.13
  Bottom 0.254: OUT5-6.7 69.05,121.91 65.24,118.09 65.24,113.02 67.14,113.02 IC5.13
N$139
  Top 0.254: 27.14,111.11 27.14,97.14 RN3.2 | 27.14,111.11 28.41,112.38 IC2.13 | 27.14,111.11 27.14,120.64 28.41,121.91 OUT1-2.15
N$140
  Top 0.254: IC5.2 60.8,113.02 62.7,114.92 62.7,123.17 61.43,124.44 OUT5-6.2
N$141  (via drill 0.61)
  Top 0.254: v83.65,100.95 83.02,101.58 v83.02,115.55 | v69.68,120 67.78,121.91 67.78,123.17 67.14,123.81 63.97,123.81 63.97,124.44 OUT5-6.4
  Bottom 0.254: v83.65,100.95 62.7,100.95 62.7,102.22 60.8,104.12 IC5.5 | v83.02,115.55 78.57,120 v69.68,120
N$142  (via drill 0.61)
  Top 0.254: v63.97,102.22 63.34,102.86 63.34,110.47 v63.97,111.11
  Bottom 0.254: v63.97,102.22 66.51,102.22 IC5.9 | v63.97,111.11 63.97,121.27 64.6,121.27 65.24,121.91 65.24,125.08 65.88,125.08 OUT5-6.6
N$143
  Bottom 0.254: IC5.12 66.51,109.84 63.34,109.84 62.7,110.47 62.7,126.35 67.14,126.35 68.41,125.08 OUT5-6.8
N$144  (via drill 0.61)
  Top 0.254: RN4.3 75.4,97.14 76.03,97.78 76.03,104.12 v75.4,104.76 75.4,110.47 v74.77,111.11 | v77.3,111.11 76.67,111.75 76.67,121.91 OUT5-6.13
  Bottom 0.254: v75.4,104.76 79.21,104.76 IC6.10 | v74.77,111.11 v77.3,111.11
N$145  (via drill 0.61)
  Top 0.254: RN4.4 72.86,97.14 74.77,99.05 74.77,100.31 74.13,100.95 70.95,100.95 70.95,105.39 72.22,106.67 IC6.4 | v77.3,107.3 78.57,108.57 78.57,111.75 77.3,113.02 77.3,119.36 77.94,120 77.94,123.81 76.03,123.81 74.77,122.54 OUT5-6.11
  Bottom 0.254: v77.3,107.3 74.13,107.3 IC6.4
N$146  (via drill 0.61)
  Top 0.254: v76.67,93.97 76.67,106.03 76.03,106.67 76.03,120.64 v75.4,121.27 | IC6.1 72.22,115.55 71.59,116.19 71.59,121.91 OUT5-6.9
  Bottom 0.254: v76.67,93.97 72.22,93.97 70.95,95.23 RN4.5 | v75.4,121.27 73.49,121.27 72.22,122.54 OUT5-6.9
N$147
  Top 0.254: IC6.2 74.13,112.38 75.4,113.65 75.4,119.36 72.86,121.91 72.86,123.17 71.59,124.44 OUT5-6.10
N$148  (via drill 0.61)
  Top 0.254: v86.83,102.22 v86.83,115.55
  Bottom 0.254: v86.83,102.22 81.75,102.22 IC6.9 | v86.83,115.55 81.11,121.27 78.57,121.27 77.94,121.91 77.94,124.44 76.67,124.44 OUT5-6.14
N$149
  Bottom 0.254: IC6.12 81.75,109.84 84.29,109.84 88.1,113.65 88.1,120.64 84.92,120.64 80.48,125.08 79.84,125.08 OUT5-6.16
N$150
  Top 0.254: RN4.9 60.16,97.14 58.26,99.05 58.26,113.02 59.52,114.28 IC5.1 60.16,115.55 60.16,120.64 61.43,121.91 OUT5-6.1
N$151  (via drill 0.61)
  Top 0.254: v64.6,103.49 65.24,102.86 65.24,97.14 RN4.7 | OUT5-6.5 66.51,121.91 65.24,120.64 65.24,114.92 66.51,113.65 69.68,113.65 69.68,106.67 68.41,105.39 IC5.10
  Bottom 0.254: v64.6,103.49 65.88,104.76 66.51,104.76 IC5.10
N$152  (via drill 0.61)
  Top 0.254: v85.56,106.03 85.56,118.09 86.19,118.73 86.19,120 84.92,121.27 81.11,121.27 81.11,125.08 79.84,126.35 74.13,126.35 74.13,125.72 OUT5-6.12
  Bottom 0.254: v85.56,106.03 74.13,106.03 73.49,105.39 IC6.5
N$153  (via drill 0.61)
  Top 0.254: v83.02,97.78 84.92,99.68 84.92,102.22 84.29,102.86 84.29,109.84 84.92,110.47 v84.92,119.36 | IC6.13 79.84,113.02 77.94,114.92 77.94,118.73 79.21,120 79.21,121.91 OUT5-6.15
  Bottom 0.254: v83.02,97.78 79.84,97.78 78.57,96.5 RN4.2 | v84.92,119.36 81.75,122.54 79.84,122.54 OUT5-6.15
N$154
  Top 0.254: OUT3-4.3 38.57,121.91 37.3,120.64 37.3,112.38 36.03,111.11 32.86,111.11 32.86,109.2 34.12,107.94 IC3.4
  Bottom 0.254: RN1.8 37.94,92.69 39.2,93.97 39.2,97.14 38.57,97.14 36.66,99.05 36.66,106.67 35.4,106.67 IC3.4
N$155
  Top 0.254: OUT3-4.7 43.65,121.91 44.29,121.27 44.29,114.28 43.02,113.02 IC3.13
  Bottom 0.254: RN1.6 42.38,93.33 42.38,97.78 39.2,97.78 37.3,99.68 37.3,109.2 37.94,109.2 41.11,112.38 IC3.13
N$156
  Top 0.254: IC3.2 34.12,113.02 32.86,114.28 32.86,118.09 34.12,119.36 34.12,122.54 36.03,124.44 OUT3-4.2
N$157  (via drill 0.61)
  Top 0.254: v31.59,120 31.59,111.11 28.41,111.11 27.78,110.47 27.78,108.57 30.95,108.57 34.12,105.39 IC3.5
  Bottom 0.254: v31.59,120 35.4,123.81 36.66,123.81 37.94,125.08 OUT3-4.4
N$158
  Top 0.254: IC3.9 43.02,102.86 44.29,104.12 44.29,105.39 43.65,106.03 40.48,106.03 40.48,110.47 41.11,111.11 44.92,111.11 44.92,125.72 44.29,126.35 41.11,126.35 41.11,125.72 OUT3-4.6
N$159  (via drill 0.61)
  Top 0.254: v38.57,113.65 39.2,114.28 39.2,121.27 39.84,121.91 39.84,123.17 40.48,123.81 43.02,123.81 43.02,125.08 OUT3-4.8
  Bottom 0.254: v38.57,113.65 44.29,113.65 44.29,111.75 43.02,110.47 IC3.12
N$160
  Top 0.254: OUT3-4.13 51.27,121.91 51.27,108.57 54.45,105.39 IC4.10
  Bottom 0.254: RN1.3 50,93.33 50,102.86 51.91,102.86 53.81,104.76 IC4.10
N$161
  Top 0.254: 45.55,105.39 45.55,103.49 48.73,103.49 49.37,102.86 49.37,95.23 47.46,93.33 RN1.4 | 45.55,105.39 46.83,106.67 IC4.4 | 45.55,105.39 45.55,118.73 48.73,121.91 OUT3-4.11
N$162  (via drill 0.61)
  Top 0.254: v48.73,120 47.46,118.73 47.46,115.55 IC4.1
  Bottom 0.254: RN1.5 44.92,93.33 44.92,98.41 39.84,98.41 37.94,100.31 37.94,108.57 43.65,108.57 46.19,111.11 48.73,111.11 49.37,111.75 49.37,114.28 48.09,114.28 IC4.1 | v48.73,120 48.09,120 46.19,121.91 OUT3-4.9
N$163  (via drill 0.61)
  Top 0.254: v43.02,116.83 42.38,117.46 v42.38,121.27
  Bottom 0.254: v43.02,116.83 46.83,113.02 IC4.2 | v42.38,121.27 42.38,123.81 44.29,123.81 45.55,125.08 OUT3-4.10
N$164  (via drill 0.61)
  Top 0.254: v58.89,116.83 58.26,117.46 58.26,122.54 54.45,126.35 51.27,126.35 51.27,125.72 OUT3-4.14
  Bottom 0.254: v58.89,116.83 58.26,116.83 58.26,105.39 55.72,102.86 IC4.9
N$165
  Top 0.254: IC4.12 55.72,110.47 57.62,112.38 57.62,120.64 53.81,124.44 OUT3-4.16
N$166  (via drill 0.61)
  Top 0.254: v37.3,94.6 v37.3,110.47 | OUT3-4.1 36.03,121.91 34.76,120.64 34.76,115.55 IC3.1
  Bottom 0.254: v37.3,94.6 35.4,92.69 RN1.9 | v37.3,110.47 37.3,114.28 35.4,114.28 IC3.1
N$167
  Top 0.254: 41.11,103.49 41.74,104.12 IC3.10 | 41.11,103.49 40.48,102.86 40.48,93.97 39.84,93.33 RN1.7 | 41.11,103.49 39.84,104.76 39.84,120.64 41.11,121.91 OUT3-4.5
N$168
  Top 0.254: IC4.5 48.09,105.39 50,107.3 50,123.17 48.73,124.44 OUT3-4.12
N$169  (via drill 0.61)
  Top 0.254: v56.98,100.95 v56.98,108.57 | v52.54,114.92 52.54,120.64 53.81,121.91 OUT3-4.15
  Bottom 0.254: v56.98,100.95 56.98,99.05 56.35,98.41 52.54,98.41 52.54,93.33 RN1.2 | v56.98,108.57 56.98,111.75 55.72,111.75 IC4.13 54.45,113.02 v52.54,114.92
N$170  (via drill 0.61)
  Top 0.254: RN2.8 66.51,55.23 66.51,81.27 OUT7-8.3 | v60.16,55.87 60.16,64.12 62.06,66.03 IC7.4
  Bottom 0.254: v60.16,55.87 64.6,55.87 65.88,54.59 RN2.8
N$171
  Top 0.254: RN2.6 71.59,55.23 72.22,55.87 72.22,64.75 71.59,65.39 68.41,65.39 68.41,69.83 69.68,71.11 IC7.13 70.95,72.38 72.22,73.64 72.22,80.63 71.59,81.27 OUT7-8.7
N$172
  Top 0.254: IC7.2 62.06,72.38 60.8,73.64 60.8,80.63 63.97,83.8 OUT7-8.2
N$173  (via drill 0.61)
  Top 0.254: v58.89,64.12 58.26,64.75 v58.26,81.9
  Bottom 0.254: v58.89,64.12 61.43,64.12 IC7.5 | v58.26,81.9 59.52,83.17 64.6,83.17 65.88,84.44 OUT7-8.4
N$174  (via drill 0.61)
  Top 0.254: v57.62,62.85 56.35,64.12 v56.35,80
  Bottom 0.254: v57.62,62.85 67.78,62.85 69.05,61.58 IC7.9 | v56.35,80 56.98,80.63 67.14,80.63 67.78,81.27 67.78,84.44 68.41,84.44 OUT7-8.6
N$175
  Top 0.254: IC7.12 70.95,69.83 72.86,71.74 72.86,82.53 71.59,83.8 OUT7-8.8
N$176
  Top 0.254: OUT7-8.13 79.21,81.27 79.21,55.23 RN2.3
  Bottom 0.254: RN2.3 79.21,55.23 79.21,64.12 81.75,64.12 IC8.10
N$177
  Bottom 0.254: RN2.4 76.67,55.23 77.3,55.23 77.3,64.75 76.03,66.03 IC8.4 74.77,67.3 72.86,67.3 72.86,74.92 76.03,78.09 76.67,78.09 76.67,81.27 OUT7-8.11
N$178
  Top 0.254: 73.49,74.28 73.49,81.9 OUT7-8.9 | 73.49,74.28 73.49,55.87 74.13,55.23 RN2.5 | 73.49,74.28 74.13,74.28 IC8.1
N$179
  Bottom 0.254: IC8.2 76.03,72.38 77.94,74.28 77.94,83.17 76.03,83.17 74.77,84.44 OUT7-8.10
N$180  (via drill 0.61)
  Top 0.254: v77.94,52.05 77.94,82.53 79.21,83.8 OUT7-8.14
  Bottom 0.254: v77.94,52.05 80.48,52.05 80.48,59.04 82.38,60.95 IC8.9
N$181
  Bottom 0.254: IC8.12 81.75,69.2 80.48,67.93 74.13,67.93 73.49,68.56 73.49,70.47 76.67,70.47 80.48,74.28 80.48,84.44 81.11,84.44 OUT7-8.16
N$182
  Top 0.254: 62.7,80 62.7,74.92 IC7.1 | 62.7,80 63.97,81.27 OUT7-8.1 | 62.7,80 65.24,77.45 65.24,56.5 63.97,55.23 RN2.9
N$183
  Top 0.254: 69.05,62.85 69.68,63.48 IC7.10 | 69.05,62.85 68.41,62.21 68.41,55.87 69.05,55.23 RN2.7 | 69.05,62.85 67.78,64.12 67.78,80 69.05,81.27 OUT7-8.5
N$184  (via drill 0.61)
  Top 0.254: v59.52,65.39 60.16,66.03 v60.16,84.44
  Bottom 0.254: v59.52,65.39 72.86,65.39 74.13,64.12 IC8.5 | v60.16,84.44 61.43,85.71 74.77,85.71 76.03,84.44 OUT7-8.12
N$185
  Top 0.254: RN2.2 81.75,55.23 81.11,55.87 81.11,69.83 82.38,71.11 IC8.13 83.65,72.38 84.92,73.64 84.92,78.09 81.75,81.27 OUT7-8.15
OA1
  Top 0.254: A1-K1.18 5.55,78.09 6.82,79.36 6.82,81.9 JP1.1
  Bottom 0.254: IC1.3 8.09,109.84 7.46,109.2 6.82,109.2 2.38,104.76 2.38,84.44 6.82,84.44 JP1.1
OB1
  Top 0.254: 8.09,78.09 9.36,79.36 9.36,81.9 JP1.2 | 8.09,78.09 A1-K1.17 8.09,78.09 | 8.09,78.09 8.09,97.14 7.46,97.78 7.46,100.31 8.73,101.58 IC1.6
OB2
  Top 0.254: A2-K2.17 41.11,38.72 42.38,39.99 42.38,42.53 JP2.2
OC  (via drill 0.61)
  Top 0.254: v11.9,31.73 11.9,31.1 14.44,28.56 IC9.8
  Bottom 0.254: v11.9,31.73 10,33.64 7.46,33.64 OC.1 6.82,34.27 5.55,34.27 | 5.55,34.27 5.55,36.81 6.18,37.45 16.98,37.45 18.89,35.55 IC9.5 | 5.55,34.27 5.55,27.93 10,23.48 11.9,23.48 15.71,19.67 30.95,19.67 40.48,10.14 47.46,10.14 47.46,5.07 48.09,4.43 59.52,4.43 60.8,5.7 IN5-6.1
OC1
  Top 0.254: A1-K1.16 10.63,78.09 11.9,79.36 11.9,81.9 JP1.3 11.9,84.44 18.25,90.79 18.25,98.41 17.62,99.05 IC1.8
OD1
  Top 0.254: A1-K1.15 13.17,78.09 14.44,79.36 14.44,81.9 JP1.4
  Bottom 0.254: IC1.11 15.71,107.3 14.44,108.57 7.46,108.57 3.01,104.12 3.01,85.71 13.17,85.71 14.44,84.44 JP1.4
OD2  (via drill 0.61)
  Top 0.254: A2-K2.15 46.19,38.72 47.46,39.99 47.46,42.53 JP2.4 47.46,45.07 52.54,50.15 52.54,87.61 v53.81,88.89
  Bottom 0.254: v53.81,88.89 53.81,97.14 54.45,97.78 57.62,97.78 57.62,99.68 59.52,101.58 IC5.6
OE1
  Top 0.254: JP1.5 16.98,81.9 16.98,79.36 15.71,78.09 A1-K1.14 15.71,75.55 15.71,74.92 23.96,74.92 24.6,75.55 24.6,78.09 25.87,79.36 25.87,109.84 23.33,109.84 IC2.3
OE2  (via drill 0.61)
  Top 0.254: A2-K2.14 48.73,38.72 50,39.99 50,42.53 JP2.5 50,45.07 53.18,48.24 53.18,86.34 v55.08,88.25 | v69.05,90.79 69.05,98.41 68.41,99.05 IC5.8
  Bottom 0.254: v69.05,90.79 66.51,88.25 v55.08,88.25
OF1
  Top 0.254: A1-K1.13 18.25,78.09 19.52,79.36 19.52,81.9 JP1.6
  Bottom 0.254: IC2.6 20.79,102.22 19.52,100.95 8.09,100.95 7.46,100.31 7.46,97.78 15.08,97.78 15.71,97.14 15.71,85.71 18.25,85.71 19.52,84.44 JP1.6
OF2  (via drill 0.61)
  Top 0.254: JP2.6 52.54,42.53 52.54,39.99 51.27,38.72 A2-K2.13 51.27,36.18 51.27,34.27 84.92,34.27 88.1,37.45 88.1,100.31 86.83,100.31 85.56,101.58 v85.56,103.49
  Bottom 0.254: v85.56,103.49 71.59,103.49 68.41,106.67 IC5.11
OH1  (via drill 0.61)
  Top 0.254: A1-K1.12 20.79,78.09 22.06,79.36 22.06,81.9 JP1.7 22.06,84.44 23.33,85.71 23.33,97.14 v24.6,98.41
  Bottom 0.254: v24.6,98.41 27.14,98.41 28.41,99.68 IC2.8
OH2
  Top 0.254: A2-K2.12 53.81,38.72 55.08,39.99 55.08,42.53 JP2.7
  Bottom 0.254: IC6.3 74.13,109.84 75.4,108.57 84.92,108.57 88.1,105.39 88.1,40.62 56.98,40.62 55.08,42.53 JP2.7
OJ1  (via drill 0.61)
  Top 0.254: A1-K1.11 23.33,78.09 24.6,79.36 24.6,81.9 JP1.8 | v30.95,85.71 30.95,93.33 31.59,93.97 31.59,105.39 30.32,106.67 IC2.11
  Bottom 0.254: v30.95,85.71 25.87,85.71 24.6,84.44 JP1.8
OJ2  (via drill 0.61)
  Top 0.254: A2-K2.11 56.35,38.72 57.62,39.99 57.62,42.53 JP2.8 | v75.4,79.36 75.4,85.08 74.13,86.34 74.13,97.14 75.4,98.41 75.4,100.95 74.13,102.22 IC6.6
  Bottom 0.254: v75.4,79.36 72.22,76.19 72.22,67.93 59.52,67.93 53.81,62.21 53.81,46.34 56.35,46.34 57.62,45.07 JP2.8
OK1  (via drill 0.61)
  Top 0.254: A1-K1.10 25.87,78.09 27.14,79.36 27.14,81.9 JP1.9 | v36.03,90.16 36.03,95.23 36.66,95.87 36.66,107.94 35.4,109.2 IC3.3
  Bottom 0.254: v36.03,90.16 32.86,86.98 25.23,86.98 23.33,85.08 23.33,80.63 25.87,80.63 27.14,81.9 JP1.9
OK2  (via drill 0.61)
  Top 0.254: JP2.9 60.16,42.53 60.16,39.99 58.89,38.72 A2-K2.10 58.89,36.18 58.89,34.91 84.29,34.91 86.19,36.81 86.19,98.41 v86.83,99.05
  Bottom 0.254: v86.83,99.05 82.38,99.05 81.75,99.68 IC6.8
OL1  (via drill 0.61)
  Top 0.254: L1-V1.18 30.95,78.09 29.68,79.36 29.68,81.9 JP1.10 | v33.49,81.27 33.49,93.33 32.86,93.97 32.86,100.31 34.12,101.58 IC3.6
  Bottom 0.254: v33.49,81.27 32.86,80.63 30.95,80.63 29.68,81.9 JP1.10
OL2  (via drill 0.61)
  Top 0.254: L2-V2.18 63.97,38.72 62.7,39.99 62.7,42.53 JP2.10 62.7,45.07 65.24,47.61 65.24,55.23 65.88,55.87 65.88,78.09 65.24,78.72 65.24,90.79 v67.78,93.33 | v77.94,99.68 77.94,104.76 79.84,106.67 IC6.11
  Bottom 0.254: v77.94,99.68 76.03,97.78 69.68,97.78 69.05,97.14 69.05,93.33 v67.78,93.33
OM1
  Top 0.254: JP1.11 32.22,81.9 32.22,79.36 33.49,78.09 L1-V1.17 33.49,75.55 33.49,74.92 41.74,74.92 42.38,75.55 42.38,78.09 41.11,79.36 41.11,98.41 41.74,99.05 IC3.8
OM2  (via drill 0.61)
  Top 0.254: L2-V2.17 66.51,38.72 65.24,39.99 65.24,42.53 JP2.11 | v55.08,49.52 v55.08,68.56
  Bottom 0.254: v55.08,68.56 60.8,68.56 61.43,69.2 IC7.3 | v55.08,49.52 58.26,46.34 63.97,46.34 65.24,45.07 JP2.11
ON1  (via drill 0.61)
  Top 0.254: L1-V1.16 36.03,78.09 34.76,79.36 34.76,81.9 JP1.12 | v43.65,90.16 43.65,93.33 44.92,94.6 44.92,106.03 43.65,107.3 IC3.11
  Bottom 0.254: v43.65,90.16 39.2,85.71 36.03,85.71 34.76,84.44 JP1.12
ON2
  Top 0.254: JP2.12 67.78,42.53 67.78,39.99 69.05,38.72 L2-V2.16 68.41,36.81 68.41,35.55 63.34,35.55 61.43,37.45 61.43,45.7 62.7,46.98 62.7,55.23 60.8,57.13 60.8,59.67 62.06,60.95 IC7.6
OP1
  Top 0.254: L1-V1.15 38.57,78.09 37.3,79.36 37.3,81.9 JP1.13
  Bottom 0.254: IC4.3 48.09,109.2 49.37,107.94 49.37,95.23 48.09,95.23 46.19,93.33 46.19,80 44.29,80 43.02,78.72 40.48,78.72 39.2,77.45 L1-V1.15
OP2
  Top 0.254: IC7.8 70.32,58.41 70.32,45.07 JP2.13 70.32,42.53 70.32,39.99 71.59,38.72 L2-V2.15
OR1  (via drill 0.61)
  Top 0.254: L1-V1.14 41.11,78.09 39.84,79.36 39.84,81.9 JP1.14 39.84,84.44 38.57,85.71 38.57,100.31 v39.2,100.95
  Bottom 0.254: v39.2,100.95 44.92,100.95 46.19,102.22 IC4.6
OR2
  Top 0.254: L2-V2.14 74.13,38.72 72.86,39.99 72.86,42.53 JP2.14 72.86,45.07 72.86,65.39 71.59,66.66 IC7.11
OS1  (via drill 0.61)
  Top 0.254: L1-V1.13 43.65,78.09 42.38,79.36 42.38,81.9 JP1.15 | v56.35,86.98 56.35,98.41 55.72,99.05 IC4.8
  Bottom 0.254: v56.35,86.98 56.35,81.27 50.63,81.27 48.73,79.36 46.19,79.36 44.29,77.45 L1-V1.13
OS2
  Top 0.254: L2-V2.13 76.67,38.72 75.4,39.99 75.4,42.53 JP2.15
  Bottom 0.254: IC8.3 76.67,69.2 81.11,73.64 81.11,75.55 86.19,75.55 87.46,74.28 87.46,41.26 76.67,41.26 75.4,42.53 JP2.15
OT2
  Top 0.254: L2-V2.12 79.21,38.72 77.94,39.99 77.94,42.53 JP2.16
  Bottom 0.254: IC8.6 74.13,61.58 72.86,60.31 61.43,60.31 57.62,56.5 57.62,48.24 74.77,48.24 77.94,45.07 JP2.16
OU1  (via drill 0.61)
  Top 0.254: L1-V1.11 48.73,78.09 47.46,79.36 47.46,81.9 JP1.17 47.46,84.44 51.27,88.25 51.27,93.33 51.91,93.97 51.91,103.49 v51.27,104.12
  Bottom 0.254: v51.27,104.12 51.91,104.12 54.45,106.67 IC4.11
OU2
  Top 0.254: L2-V2.11 81.75,38.72 80.48,39.99 80.48,42.53 JP2.17
  Bottom 0.254: IC8.8 83.02,58.41 83.02,46.34 81.75,46.34 80.48,45.07 JP2.17
OV1  (via drill 0.61)
  Top 0.254: L1-V1.10 51.27,78.09 50,79.36 50,81.9 JP1.18 | v55.08,83.8 63.97,92.69 63.97,97.14 62.7,98.41 62.7,107.3 60.8,109.2 IC5.3
  Bottom 0.254: v55.08,83.8 50.63,83.8 JP1.18
OV2
  Top 0.254: IC8.11 83.65,66.03 84.92,64.75 84.92,57.13 83.02,55.23 83.02,45.07 JP2.18 83.02,42.53 83.02,39.99 84.29,38.72 L2-V2.10
P1  (via drill 0.61)
  Top 0.254: L1-V1.4 38.57,67.93 37.3,66.66 37.3,64.12 JP3.13 37.3,61.58 39.84,59.04 39.84,54.59 SIDE1.30 | v20.79,38.09 20.79,8.88 IN1-2.10
  Bottom 0.254: v20.79,38.09 32.86,50.15 37.94,50.15 38.57,50.78 38.57,53.96 39.2,53.96 SIDE1.30
P2
  Top 0.254: L2-V2.4 71.59,28.56 70.32,27.29 70.32,24.75 JP4.13 70.32,22.21 70.32,19.04 69.05,17.77 SIDE2.24
  Bottom 0.254: IN3-4.13 51.91,5.7 53.18,6.97 58.26,6.97 62.06,10.78 81.11,10.78 83.65,13.32 83.65,20.94 71.59,20.94 70.32,22.21 JP4.13
R1  (via drill 0.61)
  Top 0.254: 41.11,67.93 39.84,66.66 39.84,64.12 JP3.14 | 41.11,67.93 L1-V1.5 41.11,67.93 | v23.33,60.31 23.33,26.02 24.6,24.75 24.6,10.14 23.33,8.88 IN1-2.12 | 41.11,67.93 41.11,53.33 40.48,52.69 36.66,52.69 35.4,53.96 SIDE1.26
  Bottom 0.254: v23.33,60.31 38.57,60.31 39.84,61.58 JP3.14
R2
  Top 0.254: L2-V2.5 74.13,28.56 72.86,27.29 72.86,24.75 JP4.14 72.86,22.21 71.59,20.94 71.59,17.77 SIDE2.26 71.59,16.5 70.32,15.22 70.32,13.32 62.06,13.32 54.45,5.7 IN3-4.15
S1  (via drill 0.61)
  Top 0.254: L1-V1.6 43.65,67.93 42.38,66.66 42.38,64.12 JP3.15 42.38,61.58 42.38,54.59 SIDE1.32 42.38,53.33 41.11,52.05 41.11,50.78 35.4,45.07 35.4,16.5 v29.68,10.78
  Bottom 0.254: v29.68,10.78 29.05,10.78 26.51,8.24 IN1-2.14
S2
  Top 0.254: L2-V2.6 76.67,28.56 75.4,27.29 75.4,24.75 JP4.15 75.4,22.21 75.4,19.04 74.13,17.77 SIDE2.28
  Bottom 0.254: IN3-4.10 46.19,7.61 44.92,6.33 44.92,3.16 79.84,3.16 84.92,8.24 84.92,27.93 78.57,27.93 77.3,29.2 L2-V2.6
T1
  Top 0.254: L1-V1.7 46.19,67.93 44.92,66.66 44.92,64.12 JP3.16 44.92,61.58 44.92,54.59 SIDE1.34
T2
  Top 0.254: L2-V2.7 79.21,28.56 77.94,27.29 77.94,24.75 JP4.16 77.94,22.21 76.67,20.94 76.67,17.77 SIDE2.30
  Bottom 0.254: IN3-4.12 48.73,8.88 48.73,13.32 62.06,13.32 62.7,13.96 62.7,18.4 74.77,18.4 76.03,17.13 SIDE2.30
U1  (via drill 0.61)
  Top 0.254: L1-V1.8 48.73,67.93 47.46,66.66 47.46,64.12 JP3.17 | v28.41,17.77 28.41,8.88 IN1-2.16 | v8.09,59.04 6.82,57.77 6.82,54.59 SIDE1.4
  Bottom 0.254: v28.41,17.77 27.14,19.04 11.9,19.04 4.28,26.66 4.28,50.15 7.46,50.15 8.09,50.78 8.09,53.33 6.82,53.33 SIDE1.4 | v8.09,59.04 44.92,59.04 47.46,61.58 JP3.17
U2
  Top 0.254: L2-V2.8 81.75,28.56 80.48,27.29 80.48,24.75 JP4.17 80.48,22.21 81.75,20.94 81.75,17.77 SIDE2.34
  Bottom 0.254: IN3-4.14 51.91,8.24 55.72,12.05 78.57,12.05 80.48,13.96 80.48,17.13 81.11,17.13 SIDE2.34
V1
  Top 0.254: L1-V1.9 51.27,67.93 50,66.66 50,64.12 JP3.18
  Bottom 0.254: IN3-4.1 36.03,6.33 29.68,12.68 9.36,12.68 2.38,19.67 2.38,53.96 3.65,53.96 SIDE1.2 4.28,54.59 4.28,63.48 6.18,65.39 48.73,65.39 50,64.12 JP3.18
V2
  Top 0.254: L2-V2.9 84.29,28.56 83.02,27.29 83.02,24.75 JP4.18 83.02,22.21 83.02,16.5 82.38,15.86 79.21,15.86 79.21,16.5 SIDE2.32
  Bottom 0.254: IN3-4.16 54.45,8.24 57.62,11.41 80.48,11.41 83.02,13.96 83.02,18.4 79.84,18.4 79.21,17.77 SIDE2.32
VCC  (via drill 0.61)
  Top 0.305: IC8.14 82.38,74.92 81.75,75.55 81.75,76.19 BYP8.1 81.75,77.45 80.48,78.72 80.48,94.6 RN4.1 80.48,97.14 82.38,99.05 82.38,113.02 81.11,114.28 IC6.14 79.84,115.55 79.84,116.19 79.21,116.83 BYP6.1 | BYP5.1 66.51,116.83 67.14,116.19 67.14,115.55 IC5.14 | IC7.14 69.68,74.92 69.05,75.55 69.05,76.19 BYP7.1 69.05,77.45 70.32,78.72 v70.32,92.06 | BYP4.1 53.81,116.83 54.45,116.19 54.45,115.55 IC4.14 | BYP3.1 41.11,116.83 41.74,116.19 41.74,115.55 IC3.14 | BYP1.1 15.71,116.83 16.35,116.19 16.35,115.55 IC1.14 | BYP2.1 28.41,116.83 29.05,116.19 29.05,115.55 IC2.14 | POWER.2 32.22,17.13 32.22,20.3 POWER2.2 32.22,22.84 32.22,27.93 BYP9.1 | A2-K2.18 38.57,38.72 39.84,39.99 39.84,42.53 JP2.1 | IC9.1 29.68,33.64 29.68,28.56 IC9.14 | RN3.1 29.68,94.6 28.41,93.33 28.41,38.09 27.14,36.81 27.14,36.18 IC9.2
  Bottom 0.305: RN2.1 84.29,55.23 84.29,57.77 84.92,58.41 84.92,73.64 83.65,73.64 IC8.14 | IC5.14 69.05,114.92 70.32,116.19 77.3,116.19 78.57,117.46 BYP6.1 | RN1.1 55.72,92.06 v70.32,92.06 76.67,92.06 79.84,95.23 RN4.1 | 31.59,114.28 30.32,114.28 IC2.14 | 31.59,114.28 32.22,114.28 32.22,98.41 30.32,96.5 RN3.1 | IC1.14 18.25,114.92 19.52,116.19 26.51,116.19 27.78,117.46 BYP2.1 | 31.59,114.28 33.49,116.19 39.2,116.19 40.48,117.46 BYP3.1 41.11,118.09 43.65,118.09 45.55,116.19 51.91,116.19 53.18,117.46 BYP4.1 | BYP10.1 8.73,15.86 11.27,13.32 29.68,13.32 31.59,15.22 POWER.2 | IC9.3 25.23,34.27 26.51,34.27 IC9.2 27.78,34.27 29.05,34.27 IC9.1 30.32,35.55 36.66,35.55 37.94,36.81 A2-K2.18 | IC9.13 27.78,26.66 29.05,26.66 IC9.14 30.32,27.93 30.95,27.93 31.59,28.56 BYP9.1 | IC7.14 69.05,74.28 65.24,70.47 55.08,70.47 51.27,66.66 51.27,46.34 41.11,46.34 39.84,45.07 JP2.1

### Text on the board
Top: Component Side | PA8PDP/VRS
Bottom: Solder Side
tPlace: 16 | 16 | 16 | 1 | 1 | 1 | 1 | 1 | 1 | 16 | 1 | 34 | 1 | 1 | 34 | 1 | 16 | 16 | 16 | 1 | 1 | 1
tNames: OUT3-4 | OUT5-6 | IC1 | IC2 | IC3 | IC4 | IC5 | IC6 | RN3 | RN4 | RN1 | OUT7-8 | JP1 | A1-K1 | L1-V1 | IC7 | IC8 | JP3 | SIDE1 | RN2 | JP2 | A2-K2 | L2-V2 | IC9 | C1 | BYP9 | JP4 | R1 | SIDE2
tValues: 74LS125N | 74LS125N | 74LS125N | 74LS125N | 74LS125N | 74LS125N | A1-K1 | L1-V1 | 74LS125N | 74LS125N | FlipChip Tester - Rev.1 | A2-K2 | L2-V2 | 74LS10N | 0.1uf | 0.1uf | 1K | - | + | + | -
